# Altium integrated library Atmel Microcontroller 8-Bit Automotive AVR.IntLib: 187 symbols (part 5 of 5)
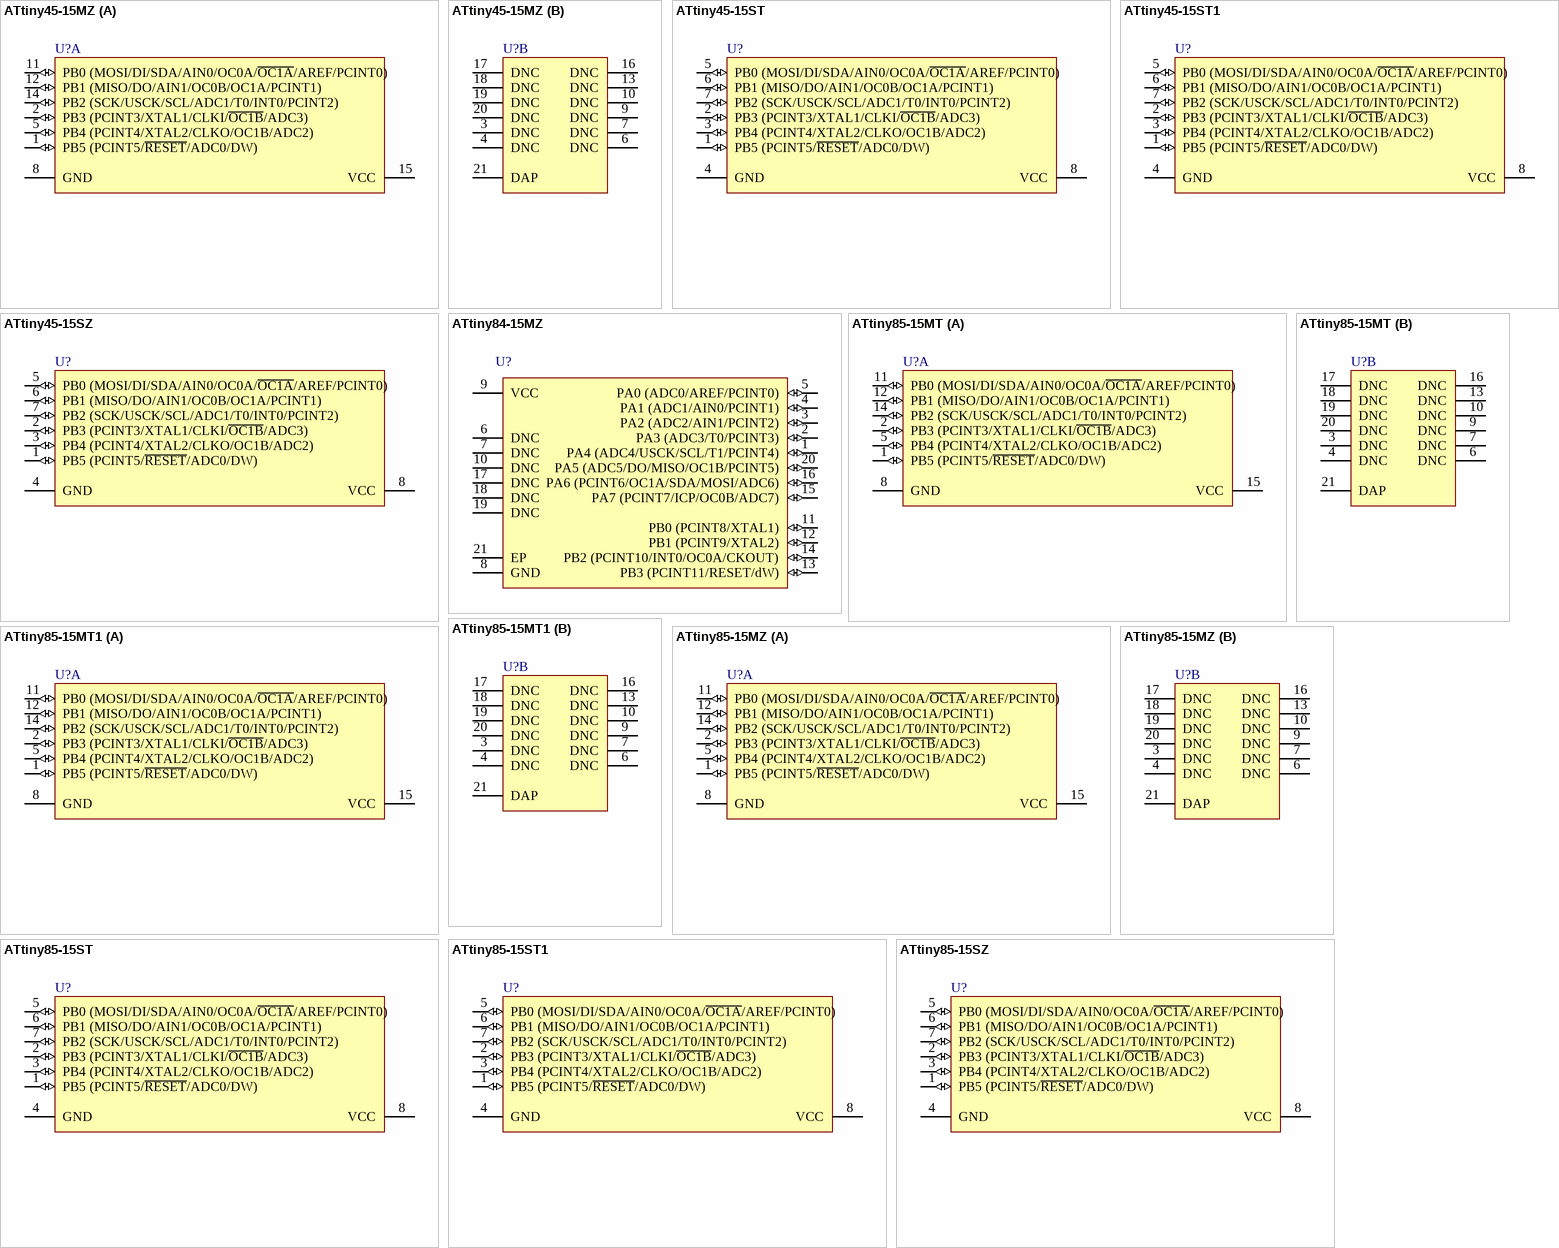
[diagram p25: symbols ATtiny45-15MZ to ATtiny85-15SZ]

## ATtiny85-15MT1
designator U?
8-bit Automotive AVR Microcontroller, 8KB Flash, 512 Bytes EEPROM, 512 Bytes SRAM, Automotive Grade (-40°C to +105°C), 20-Pin VQFN
footprint 20PC_N (QFN, 20-Leads, Body 4x4mm, Pitch 0.5mm, IPC Medium Density)
footprint 20PC_L (QFN, 20-Leads, Body 4x4mm, Pitch 0.5mm, IPC High Density)
footprint 20PC_M (QFN, 20-Leads, Body 4x4mm, Pitch 0.5mm, IPC Low Density)
part A pins: 1 PB5 (PCINT5/~{RESET}/ADC0/DW) (io), 2 PB3 (PCINT3/XTAL1/CLKI/~{OC1B}/ADC3) (io), 5 PB4 (PCINT4/XTAL2/CLKO/OC1B/ADC2) (io), 8 GND (power), 11 PB0 (MOSI/DI/SDA/AIN0/OC0A/~{OC1A}/AREF/PCINT0) (io), 12 PB1 (MISO/DO/AIN1/OC0B/OC1A/PCINT1) (io), 14 PB2 (SCK/USCK/SCL/ADC1/T0/INT0/PCINT2) (io), 15 VCC (power)
part B pins: 3 DNC, 4 DNC, 6 DNC, 7 DNC, 9 DNC, 10 DNC, 13 DNC, 16 DNC, 17 DNC, 18 DNC, 19 DNC, 20 DNC, 21 DAP

## ATtiny85-15MZ
designator U?
8-bit Automotive AVR Microcontroller, 8KB Flash, 512 Bytes EEPROM, 512 Bytes SRAM, Automotive Grade (-40°C to +125°C), 20-Pin VQFN
footprint 20PC_N (QFN, 20-Leads, Body 4x4mm, Pitch 0.5mm, IPC Medium Density)
footprint 20PC_L (QFN, 20-Leads, Body 4x4mm, Pitch 0.5mm, IPC High Density)
footprint 20PC_M (QFN, 20-Leads, Body 4x4mm, Pitch 0.5mm, IPC Low Density)
part A pins: 1 PB5 (PCINT5/~{RESET}/ADC0/DW) (io), 2 PB3 (PCINT3/XTAL1/CLKI/~{OC1B}/ADC3) (io), 5 PB4 (PCINT4/XTAL2/CLKO/OC1B/ADC2) (io), 8 GND (power), 11 PB0 (MOSI/DI/SDA/AIN0/OC0A/~{OC1A}/AREF/PCINT0) (io), 12 PB1 (MISO/DO/AIN1/OC0B/OC1A/PCINT1) (io), 14 PB2 (SCK/USCK/SCL/ADC1/T0/INT0/PCINT2) (io), 15 VCC (power)
part B pins: 3 DNC, 4 DNC, 6 DNC, 7 DNC, 9 DNC, 10 DNC, 13 DNC, 16 DNC, 17 DNC, 18 DNC, 19 DNC, 20 DNC, 21 DAP

## ATtiny85-15ST
designator U?
8-bit Automotive AVR Microcontroller, 8KB Flash, 512 Bytes EEPROM, 512 Bytes SRAM, Automotive Grade (-40°C to +85°C), 8-Pin SOIC
footprint T5_N (SOP, 8-Leads, Body 5.2x5.3mm, Pitch 1.27mm, IPC Medium Density)
footprint T5_L (SOP, 8-Leads, Body 5.2x5.3mm, Pitch 1.27mm, IPC High Density)
footprint T5_M (SOP, 8-Leads, Body 5.2x5.3mm, Pitch 1.27mm, IPC Low Density)
pins: 1 PB5 (PCINT5/~{RESET}/ADC0/DW) (io), 2 PB3 (PCINT3/XTAL1/CLKI/~{OC1B}/ADC3) (io), 3 PB4 (PCINT4/XTAL2/CLKO/OC1B/ADC2) (io), 4 GND (power), 5 PB0 (MOSI/DI/SDA/AIN0/OC0A/~{OC1A}/AREF/PCINT0) (io), 6 PB1 (MISO/DO/AIN1/OC0B/OC1A/PCINT1) (io), 7 PB2 (SCK/USCK/SCL/ADC1/T0/INT0/PCINT2) (io), 8 VCC (power)

## ATtiny85-15ST1
designator U?
8-bit Automotive AVR Microcontroller, 8KB Flash, 512 Bytes EEPROM, 512 Bytes SRAM, Automotive Grade (-40°C to +105°C), 8-Pin SOIC
footprint T5_N (SOP, 8-Leads, Body 5.2x5.3mm, Pitch 1.27mm, IPC Medium Density)
footprint T5_L (SOP, 8-Leads, Body 5.2x5.3mm, Pitch 1.27mm, IPC High Density)
footprint T5_M (SOP, 8-Leads, Body 5.2x5.3mm, Pitch 1.27mm, IPC Low Density)
pins: 1 PB5 (PCINT5/~{RESET}/ADC0/DW) (io), 2 PB3 (PCINT3/XTAL1/CLKI/~{OC1B}/ADC3) (io), 3 PB4 (PCINT4/XTAL2/CLKO/OC1B/ADC2) (io), 4 GND (power), 5 PB0 (MOSI/DI/SDA/AIN0/OC0A/~{OC1A}/AREF/PCINT0) (io), 6 PB1 (MISO/DO/AIN1/OC0B/OC1A/PCINT1) (io), 7 PB2 (SCK/USCK/SCL/ADC1/T0/INT0/PCINT2) (io), 8 VCC (power)

## ATtiny85-15SZ
designator U?
8-bit Automotive AVR Microcontroller, 8KB Flash, 512 Bytes EEPROM, 512 Bytes SRAM, Automotive Grade (-40°C to +125°C), 8-Pin SOIC
footprint T5_N (SOP, 8-Leads, Body 5.2x5.3mm, Pitch 1.27mm, IPC Medium Density)
footprint T5_L (SOP, 8-Leads, Body 5.2x5.3mm, Pitch 1.27mm, IPC High Density)
footprint T5_M (SOP, 8-Leads, Body 5.2x5.3mm, Pitch 1.27mm, IPC Low Density)
pins: 1 PB5 (PCINT5/~{RESET}/ADC0/DW) (io), 2 PB3 (PCINT3/XTAL1/CLKI/~{OC1B}/ADC3) (io), 3 PB4 (PCINT4/XTAL2/CLKO/OC1B/ADC2) (io), 4 GND (power), 5 PB0 (MOSI/DI/SDA/AIN0/OC0A/~{OC1A}/AREF/PCINT0) (io), 6 PB1 (MISO/DO/AIN1/OC0B/OC1A/PCINT1) (io), 7 PB2 (SCK/USCK/SCL/ADC1/T0/INT0/PCINT2) (io), 8 VCC (power)

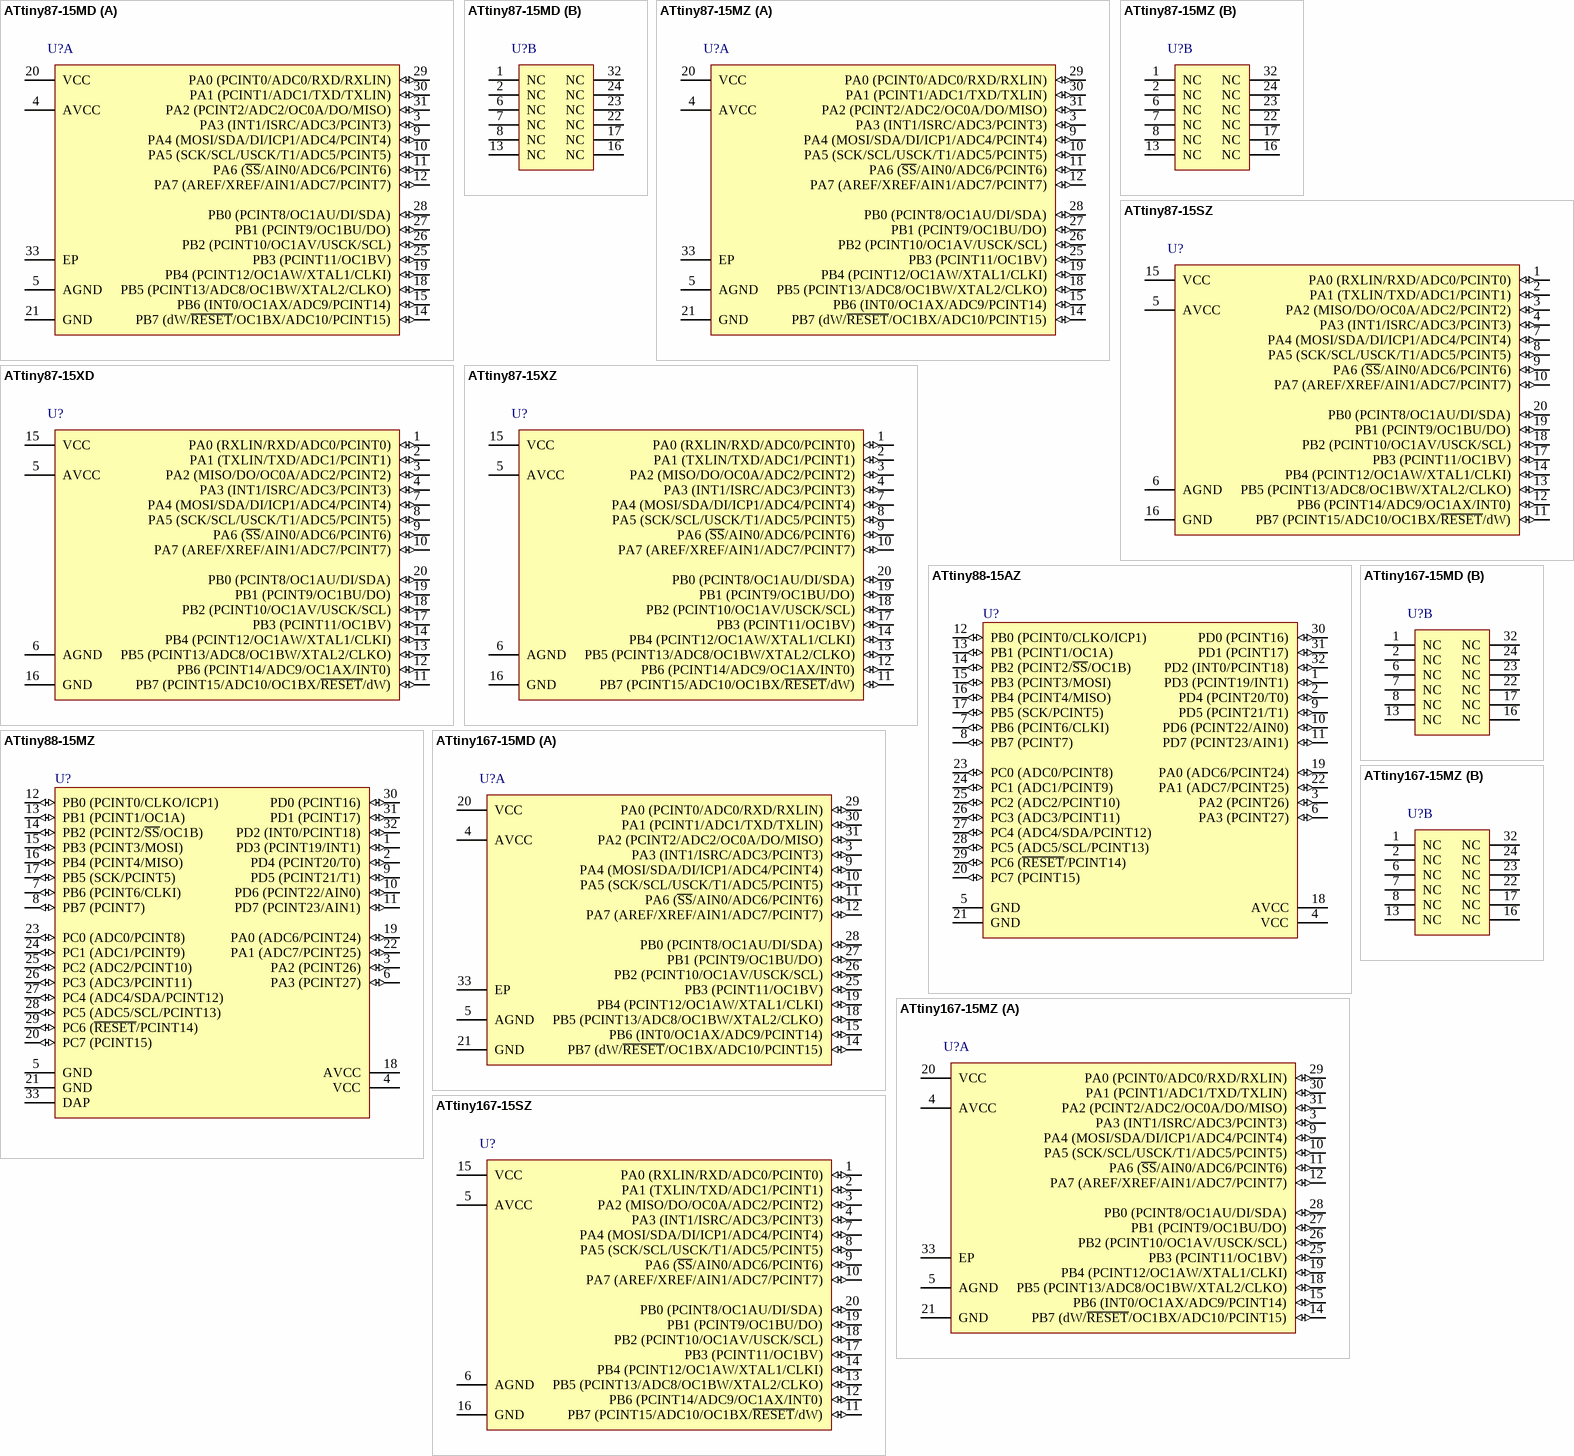
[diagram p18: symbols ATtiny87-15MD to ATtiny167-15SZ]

## ATtiny87-15MD
designator U?
8-bit Automotive AVR Microcontroller, 8KB Flash, 512 Bytes EEPROM, 512 Bytes SRAM, Extended Grade (-40°C to +150°C), 32-Pin VQFN
footprint 32PN_N (QFN, 32-Leads, Body 5x5mm, Pitch 0.5mm, IPC Medium Density)
footprint 32PN_L (QFN, 32-Leads, Body 5x5mm, Pitch 0.5mm, IPC High Density)
footprint 32PN_M (QFN, 32-Leads, Body 5x5mm, Pitch 0.5mm, IPC Low Density)
part A pins: 3 PA3 (INT1/ISRC/ADC3/PCINT3) (io), 4 AVCC (power), 5 AGND (power), 9 PA4 (MOSI/SDA/DI/ICP1/ADC4/PCINT4) (io), 10 PA5 (SCK/SCL/USCK/T1/ADC5/PCINT5) (io), 11 PA6 (~{SS}/AIN0/ADC6/PCINT6) (io), 12 PA7 (AREF/XREF/AIN1/ADC7/PCINT7) (io), 14 PB7 (dW/~{RESET}/OC1BX/ADC10/PCINT15) (io), 15 PB6 (INT0/OC1AX/ADC9/PCINT14) (io), 18 PB5 (PCINT13/ADC8/OC1BW/XTAL2/CLKO) (io), 19 PB4 (PCINT12/OC1AW/XTAL1/CLKI) (io), 20 VCC (power), 21 GND (power), 25 PB3 (PCINT11/OC1BV) (io), 26 PB2 (PCINT10/OC1AV/USCK/SCL) (io), 27 PB1 (PCINT9/OC1BU/DO) (io), 28 PB0 (PCINT8/OC1AU/DI/SDA) (io), 29 PA0 (PCINT0/ADC0/RXD/RXLIN) (io), 30 PA1 (PCINT1/ADC1/TXD/TXLIN) (io), 31 PA2 (PCINT2/ADC2/OC0A/DO/MISO) (io), 33 EP (power)
part B pins: 1 NC, 2 NC, 6 NC, 7 NC, 8 NC, 13 NC, 16 NC, 17 NC, 22 NC, 23 NC, 24 NC, 32 NC

## ATtiny87-15MZ
designator U?
8-bit Automotive AVR Microcontroller, 8KB Flash, 512 Bytes EEPROM, 512 Bytes SRAM, Automotive Grade (-40°C to +125°C), 32-Pin VQFN
footprint 32PN_N (QFN, 32-Leads, Body 5x5mm, Pitch 0.5mm, IPC Medium Density)
footprint 32PN_L (QFN, 32-Leads, Body 5x5mm, Pitch 0.5mm, IPC High Density)
footprint 32PN_M (QFN, 32-Leads, Body 5x5mm, Pitch 0.5mm, IPC Low Density)
part A pins: 3 PA3 (INT1/ISRC/ADC3/PCINT3) (io), 4 AVCC (power), 5 AGND (power), 9 PA4 (MOSI/SDA/DI/ICP1/ADC4/PCINT4) (io), 10 PA5 (SCK/SCL/USCK/T1/ADC5/PCINT5) (io), 11 PA6 (~{SS}/AIN0/ADC6/PCINT6) (io), 12 PA7 (AREF/XREF/AIN1/ADC7/PCINT7) (io), 14 PB7 (dW/~{RESET}/OC1BX/ADC10/PCINT15) (io), 15 PB6 (INT0/OC1AX/ADC9/PCINT14) (io), 18 PB5 (PCINT13/ADC8/OC1BW/XTAL2/CLKO) (io), 19 PB4 (PCINT12/OC1AW/XTAL1/CLKI) (io), 20 VCC (power), 21 GND (power), 25 PB3 (PCINT11/OC1BV) (io), 26 PB2 (PCINT10/OC1AV/USCK/SCL) (io), 27 PB1 (PCINT9/OC1BU/DO) (io), 28 PB0 (PCINT8/OC1AU/DI/SDA) (io), 29 PA0 (PCINT0/ADC0/RXD/RXLIN) (io), 30 PA1 (PCINT1/ADC1/TXD/TXLIN) (io), 31 PA2 (PCINT2/ADC2/OC0A/DO/MISO) (io), 33 EP (power)
part B pins: 1 NC, 2 NC, 6 NC, 7 NC, 8 NC, 13 NC, 16 NC, 17 NC, 22 NC, 23 NC, 24 NC, 32 NC

## ATtiny87-15SZ
designator U?
8-bit Automotive AVR Microcontroller, 8KB Flash, 512 Bytes EEPROM, 512 Bytes SRAM, Automotive Grade (-40°C to +125°C), 20-Pin SOIC
footprint 20TG_N (SOIC, 20-Leads, Body 12.8x7.5mm, Pitch 1.27mm, IPC Medium Density)
footprint 20TG_L (SOIC, 20-Leads, Body 12.8x7.5mm, Pitch 1.27mm, IPC High Density)
footprint 20TG_M (SOIC, 20-Leads, Body 12.8x7.5mm, Pitch 1.27mm, IPC Low Density)
pins: 1 PA0 (RXLIN/RXD/ADC0/PCINT0) (io), 2 PA1 (TXLIN/TXD/ADC1/PCINT1) (io), 3 PA2 (MISO/DO/OC0A/ADC2/PCINT2) (io), 4 PA3 (INT1/ISRC/ADC3/PCINT3) (io), 5 AVCC (power), 6 AGND (power), 7 PA4 (MOSI/SDA/DI/ICP1/ADC4/PCINT4) (io), 8 PA5 (SCK/SCL/USCK/T1/ADC5/PCINT5) (io), 9 PA6 (~{SS}/AIN0/ADC6/PCINT6) (io), 10 PA7 (AREF/XREF/AIN1/ADC7/PCINT7) (io), 11 PB7 (PCINT15/ADC10/OC1BX/~{RESET}/dW) (io), 12 PB6 (PCINT14/ADC9/OC1AX/INT0) (io), 13 PB5 (PCINT13/ADC8/OC1BW/XTAL2/CLKO) (io), 14 PB4 (PCINT12/OC1AW/XTAL1/CLKI) (io), 15 VCC (power), 16 GND (power), 17 PB3 (PCINT11/OC1BV) (io), 18 PB2 (PCINT10/OC1AV/USCK/SCL) (io), 19 PB1 (PCINT9/OC1BU/DO) (io), 20 PB0 (PCINT8/OC1AU/DI/SDA) (io)

## ATtiny87-15XD
designator U?
8-bit Automotive AVR Microcontroller, 8KB Flash, 512 Bytes EEPROM, 512 Bytes SRAM, Extended Grade (-40°C to +150°C), 20-Pin TSSOP
footprint 6G_N (TSOP, 20-Leads, Body 6.5x4.4mm, Pitch 0.65mm, IPC Medium Density)
footprint 6G_L (TSOP, 20-Leads, Body 6.5x4.4mm, Pitch 0.65mm, IPC High Density)
footprint 6G_M (TSOP, 20-Leads, Body 6.5x4.4mm, Pitch 0.65mm, IPC Low Density)
pins: 1 PA0 (RXLIN/RXD/ADC0/PCINT0) (io), 2 PA1 (TXLIN/TXD/ADC1/PCINT1) (io), 3 PA2 (MISO/DO/OC0A/ADC2/PCINT2) (io), 4 PA3 (INT1/ISRC/ADC3/PCINT3) (io), 5 AVCC (power), 6 AGND (power), 7 PA4 (MOSI/SDA/DI/ICP1/ADC4/PCINT4) (io), 8 PA5 (SCK/SCL/USCK/T1/ADC5/PCINT5) (io), 9 PA6 (~{SS}/AIN0/ADC6/PCINT6) (io), 10 PA7 (AREF/XREF/AIN1/ADC7/PCINT7) (io), 11 PB7 (PCINT15/ADC10/OC1BX/~{RESET}/dW) (io), 12 PB6 (PCINT14/ADC9/OC1AX/INT0) (io), 13 PB5 (PCINT13/ADC8/OC1BW/XTAL2/CLKO) (io), 14 PB4 (PCINT12/OC1AW/XTAL1/CLKI) (io), 15 VCC (power), 16 GND (power), 17 PB3 (PCINT11/OC1BV) (io), 18 PB2 (PCINT10/OC1AV/USCK/SCL) (io), 19 PB1 (PCINT9/OC1BU/DO) (io), 20 PB0 (PCINT8/OC1AU/DI/SDA) (io)

## ATtiny87-15XZ
designator U?
8-bit Automotive AVR Microcontroller, 8KB Flash, 512 Bytes EEPROM, 512 Bytes SRAM, Automotive Grade (-40°C to +125°C), 20-Pin TSSOP
footprint 6G_N (TSOP, 20-Leads, Body 6.5x4.4mm, Pitch 0.65mm, IPC Medium Density)
footprint 6G_L (TSOP, 20-Leads, Body 6.5x4.4mm, Pitch 0.65mm, IPC High Density)
footprint 6G_M (TSOP, 20-Leads, Body 6.5x4.4mm, Pitch 0.65mm, IPC Low Density)
pins: 1 PA0 (RXLIN/RXD/ADC0/PCINT0) (io), 2 PA1 (TXLIN/TXD/ADC1/PCINT1) (io), 3 PA2 (MISO/DO/OC0A/ADC2/PCINT2) (io), 4 PA3 (INT1/ISRC/ADC3/PCINT3) (io), 5 AVCC (power), 6 AGND (power), 7 PA4 (MOSI/SDA/DI/ICP1/ADC4/PCINT4) (io), 8 PA5 (SCK/SCL/USCK/T1/ADC5/PCINT5) (io), 9 PA6 (~{SS}/AIN0/ADC6/PCINT6) (io), 10 PA7 (AREF/XREF/AIN1/ADC7/PCINT7) (io), 11 PB7 (PCINT15/ADC10/OC1BX/~{RESET}/dW) (io), 12 PB6 (PCINT14/ADC9/OC1AX/INT0) (io), 13 PB5 (PCINT13/ADC8/OC1BW/XTAL2/CLKO) (io), 14 PB4 (PCINT12/OC1AW/XTAL1/CLKI) (io), 15 VCC (power), 16 GND (power), 17 PB3 (PCINT11/OC1BV) (io), 18 PB2 (PCINT10/OC1AV/USCK/SCL) (io), 19 PB1 (PCINT9/OC1BU/DO) (io), 20 PB0 (PCINT8/OC1AU/DI/SDA) (io)

## ATtiny88-15AZ
designator U?
8-bit Automotive AVR Microcontroller, 8KB Flash, 64 Bytes EEPROM, 512 Bytes SRAM, Automotive Grade (-40°C to +125°C), 32-Pin TQFP
footprint 32MA_N (Thin QFP, 32-Leads, Body 7x7mm, Pitch 0.8mm, IPC Medium Density)
footprint 32MA_L (Thin QFP, 32-Leads, Body 7x7mm, Pitch 0.8mm, IPC High Density)
footprint 32MA_M (Thin QFP, 32-Leads, Body 7x7mm, Pitch 0.8mm, IPC Low Density)
pins: 1 PD3 (PCINT19/INT1) (io), 2 PD4 (PCINT20/T0) (io), 3 PA2 (PCINT26) (io), 4 VCC (power), 5 GND (power), 6 PA3 (PCINT27) (io), 7 PB6 (PCINT6/CLKI) (io), 8 PB7 (PCINT7) (io), 9 PD5 (PCINT21/T1) (io), 10 PD6 (PCINT22/AIN0) (io), 11 PD7 (PCINT23/AIN1) (io), 12 PB0 (PCINT0/CLKO/ICP1) (io), 13 PB1 (PCINT1/OC1A) (io), 14 PB2 (PCINT2/~{SS}/OC1B) (io), 15 PB3 (PCINT3/MOSI) (io), 16 PB4 (PCINT4/MISO) (io), 17 PB5 (SCK/PCINT5) (io), 18 AVCC (power), 19 PA0 (ADC6/PCINT24) (io), 20 PC7 (PCINT15) (io), 21 GND (power), 22 PA1 (ADC7/PCINT25) (io), 23 PC0 (ADC0/PCINT8) (io), 24 PC1 (ADC1/PCINT9) (io), 25 PC2 (ADC2/PCINT10) (io), 26 PC3 (ADC3/PCINT11) (io), 27 PC4 (ADC4/SDA/PCINT12) (io), 28 PC5 (ADC5/SCL/PCINT13) (io), 29 PC6 (~{RESET}/PCINT14) (io), 30 PD0 (PCINT16) (io), 31 PD1 (PCINT17) (io), 32 PD2 (INT0/PCINT18) (io)

## ATtiny88-15MZ
designator U?
8-bit Automotive AVR Microcontroller, 8KB Flash, 64 Bytes EEPROM, 512 Bytes SRAM, Automotive Grade (-40°C to +125°C), 32-Pin VQFN
footprint 32PN_N (QFN, 32-Leads, Body 5x5mm, Pitch 0.5mm, IPC Medium Density)
footprint 32PN_L (QFN, 32-Leads, Body 5x5mm, Pitch 0.5mm, IPC High Density)
footprint 32PN_M (QFN, 32-Leads, Body 5x5mm, Pitch 0.5mm, IPC Low Density)
pins: 1 PD3 (PCINT19/INT1) (io), 2 PD4 (PCINT20/T0) (io), 3 PA2 (PCINT26) (io), 4 VCC (power), 5 GND (power), 6 PA3 (PCINT27) (io), 7 PB6 (PCINT6/CLKI) (io), 8 PB7 (PCINT7) (io), 9 PD5 (PCINT21/T1) (io), 10 PD6 (PCINT22/AIN0) (io), 11 PD7 (PCINT23/AIN1) (io), 12 PB0 (PCINT0/CLKO/ICP1) (io), 13 PB1 (PCINT1/OC1A) (io), 14 PB2 (PCINT2/~{SS}/OC1B) (io), 15 PB3 (PCINT3/MOSI) (io), 16 PB4 (PCINT4/MISO) (io), 17 PB5 (SCK/PCINT5) (io), 18 AVCC (power), 19 PA0 (ADC6/PCINT24) (io), 20 PC7 (PCINT15) (io), 21 GND (power), 22 PA1 (ADC7/PCINT25) (io), 23 PC0 (ADC0/PCINT8) (io), 24 PC1 (ADC1/PCINT9) (io), 25 PC2 (ADC2/PCINT10) (io), 26 PC3 (ADC3/PCINT11) (io), 27 PC4 (ADC4/SDA/PCINT12) (io), 28 PC5 (ADC5/SCL/PCINT13) (io), 29 PC6 (~{RESET}/PCINT14) (io), 30 PD0 (PCINT16) (io), 31 PD1 (PCINT17) (io), 32 PD2 (INT0/PCINT18) (io), 33 DAP

## ATtiny167-15MD
designator U?
8-bit Automotive AVR Microcontroller, 16KB Flash, 512 Bytes EEPROM, 512 Bytes SRAM, Extended Grade (-40°C to +150°C), 32-Pin VQFN
footprint 32PN_N (QFN, 32-Leads, Body 5x5mm, Pitch 0.5mm, IPC Medium Density)
footprint 32PN_L (QFN, 32-Leads, Body 5x5mm, Pitch 0.5mm, IPC High Density)
footprint 32PN_M (QFN, 32-Leads, Body 5x5mm, Pitch 0.5mm, IPC Low Density)
part A pins: 3 PA3 (INT1/ISRC/ADC3/PCINT3) (io), 4 AVCC (power), 5 AGND (power), 9 PA4 (MOSI/SDA/DI/ICP1/ADC4/PCINT4) (io), 10 PA5 (SCK/SCL/USCK/T1/ADC5/PCINT5) (io), 11 PA6 (~{SS}/AIN0/ADC6/PCINT6) (io), 12 PA7 (AREF/XREF/AIN1/ADC7/PCINT7) (io), 14 PB7 (dW/~{RESET}/OC1BX/ADC10/PCINT15) (io), 15 PB6 (INT0/OC1AX/ADC9/PCINT14) (io), 18 PB5 (PCINT13/ADC8/OC1BW/XTAL2/CLKO) (io), 19 PB4 (PCINT12/OC1AW/XTAL1/CLKI) (io), 20 VCC (power), 21 GND (power), 25 PB3 (PCINT11/OC1BV) (io), 26 PB2 (PCINT10/OC1AV/USCK/SCL) (io), 27 PB1 (PCINT9/OC1BU/DO) (io), 28 PB0 (PCINT8/OC1AU/DI/SDA) (io), 29 PA0 (PCINT0/ADC0/RXD/RXLIN) (io), 30 PA1 (PCINT1/ADC1/TXD/TXLIN) (io), 31 PA2 (PCINT2/ADC2/OC0A/DO/MISO) (io), 33 EP (power)
part B pins: 1 NC, 2 NC, 6 NC, 7 NC, 8 NC, 13 NC, 16 NC, 17 NC, 22 NC, 23 NC, 24 NC, 32 NC

## ATtiny167-15MZ
designator U?
8-bit Automotive AVR Microcontroller, 16KB Flash, 512 Bytes EEPROM, 512 Bytes SRAM, Automotive Grade (-40°C to +125°C), 32-Pin VQFN
footprint 32PN_N (QFN, 32-Leads, Body 5x5mm, Pitch 0.5mm, IPC Medium Density)
footprint 32PN_L (QFN, 32-Leads, Body 5x5mm, Pitch 0.5mm, IPC High Density)
footprint 32PN_M (QFN, 32-Leads, Body 5x5mm, Pitch 0.5mm, IPC Low Density)
part A pins: 3 PA3 (INT1/ISRC/ADC3/PCINT3) (io), 4 AVCC (power), 5 AGND (power), 9 PA4 (MOSI/SDA/DI/ICP1/ADC4/PCINT4) (io), 10 PA5 (SCK/SCL/USCK/T1/ADC5/PCINT5) (io), 11 PA6 (~{SS}/AIN0/ADC6/PCINT6) (io), 12 PA7 (AREF/XREF/AIN1/ADC7/PCINT7) (io), 14 PB7 (dW/~{RESET}/OC1BX/ADC10/PCINT15) (io), 15 PB6 (INT0/OC1AX/ADC9/PCINT14) (io), 18 PB5 (PCINT13/ADC8/OC1BW/XTAL2/CLKO) (io), 19 PB4 (PCINT12/OC1AW/XTAL1/CLKI) (io), 20 VCC (power), 21 GND (power), 25 PB3 (PCINT11/OC1BV) (io), 26 PB2 (PCINT10/OC1AV/USCK/SCL) (io), 27 PB1 (PCINT9/OC1BU/DO) (io), 28 PB0 (PCINT8/OC1AU/DI/SDA) (io), 29 PA0 (PCINT0/ADC0/RXD/RXLIN) (io), 30 PA1 (PCINT1/ADC1/TXD/TXLIN) (io), 31 PA2 (PCINT2/ADC2/OC0A/DO/MISO) (io), 33 EP (power)
part B pins: 1 NC, 2 NC, 6 NC, 7 NC, 8 NC, 13 NC, 16 NC, 17 NC, 22 NC, 23 NC, 24 NC, 32 NC

## ATtiny167-15SZ
designator U?
8-bit Automotive AVR Microcontroller, 16KB Flash, 512 Bytes EEPROM, 512 Bytes SRAM, Automotive Grade (-40°C to +125°C), 20-Pin SOIC
footprint 20TG_N (SOIC, 20-Leads, Body 12.8x7.5mm, Pitch 1.27mm, IPC Medium Density)
footprint 20TG_L (SOIC, 20-Leads, Body 12.8x7.5mm, Pitch 1.27mm, IPC High Density)
footprint 20TG_M (SOIC, 20-Leads, Body 12.8x7.5mm, Pitch 1.27mm, IPC Low Density)
pins: 1 PA0 (RXLIN/RXD/ADC0/PCINT0) (io), 2 PA1 (TXLIN/TXD/ADC1/PCINT1) (io), 3 PA2 (MISO/DO/OC0A/ADC2/PCINT2) (io), 4 PA3 (INT1/ISRC/ADC3/PCINT3) (io), 5 AVCC (power), 6 AGND (power), 7 PA4 (MOSI/SDA/DI/ICP1/ADC4/PCINT4) (io), 8 PA5 (SCK/SCL/USCK/T1/ADC5/PCINT5) (io), 9 PA6 (~{SS}/AIN0/ADC6/PCINT6) (io), 10 PA7 (AREF/XREF/AIN1/ADC7/PCINT7) (io), 11 PB7 (PCINT15/ADC10/OC1BX/~{RESET}/dW) (io), 12 PB6 (PCINT14/ADC9/OC1AX/INT0) (io), 13 PB5 (PCINT13/ADC8/OC1BW/XTAL2/CLKO) (io), 14 PB4 (PCINT12/OC1AW/XTAL1/CLKI) (io), 15 VCC (power), 16 GND (power), 17 PB3 (PCINT11/OC1BV) (io), 18 PB2 (PCINT10/OC1AV/USCK/SCL) (io), 19 PB1 (PCINT9/OC1BU/DO) (io), 20 PB0 (PCINT8/OC1AU/DI/SDA) (io)

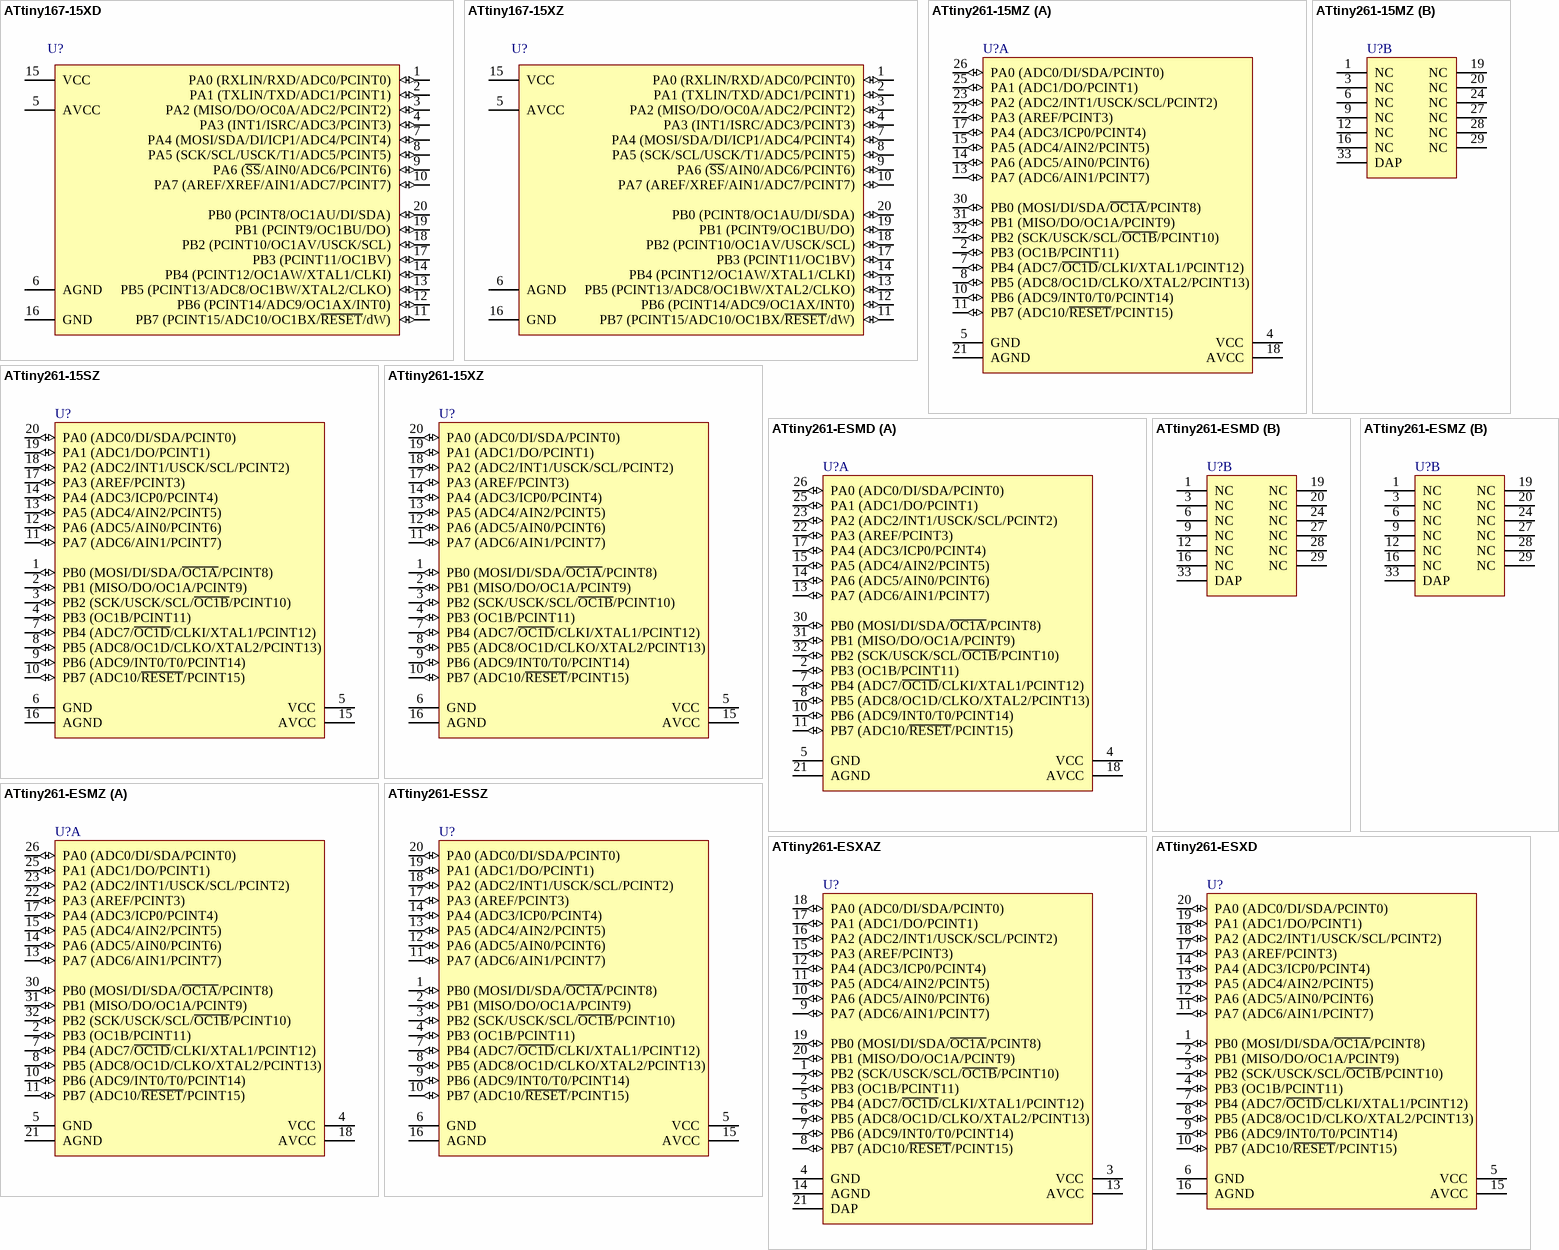
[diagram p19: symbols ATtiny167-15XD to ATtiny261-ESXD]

## ATtiny167-15XD
designator U?
8-bit Automotive AVR Microcontroller, 16KB Flash, 512 Bytes EEPROM, 512 Bytes SRAM, Extended Grade (-40°C to +150°C), 20-Pin TSSOP
footprint 6G_N (TSOP, 20-Leads, Body 6.5x4.4mm, Pitch 0.65mm, IPC Medium Density)
footprint 6G_L (TSOP, 20-Leads, Body 6.5x4.4mm, Pitch 0.65mm, IPC High Density)
footprint 6G_M (TSOP, 20-Leads, Body 6.5x4.4mm, Pitch 0.65mm, IPC Low Density)
pins: 1 PA0 (RXLIN/RXD/ADC0/PCINT0) (io), 2 PA1 (TXLIN/TXD/ADC1/PCINT1) (io), 3 PA2 (MISO/DO/OC0A/ADC2/PCINT2) (io), 4 PA3 (INT1/ISRC/ADC3/PCINT3) (io), 5 AVCC (power), 6 AGND (power), 7 PA4 (MOSI/SDA/DI/ICP1/ADC4/PCINT4) (io), 8 PA5 (SCK/SCL/USCK/T1/ADC5/PCINT5) (io), 9 PA6 (~{SS}/AIN0/ADC6/PCINT6) (io), 10 PA7 (AREF/XREF/AIN1/ADC7/PCINT7) (io), 11 PB7 (PCINT15/ADC10/OC1BX/~{RESET}/dW) (io), 12 PB6 (PCINT14/ADC9/OC1AX/INT0) (io), 13 PB5 (PCINT13/ADC8/OC1BW/XTAL2/CLKO) (io), 14 PB4 (PCINT12/OC1AW/XTAL1/CLKI) (io), 15 VCC (power), 16 GND (power), 17 PB3 (PCINT11/OC1BV) (io), 18 PB2 (PCINT10/OC1AV/USCK/SCL) (io), 19 PB1 (PCINT9/OC1BU/DO) (io), 20 PB0 (PCINT8/OC1AU/DI/SDA) (io)

## ATtiny167-15XZ
designator U?
8-bit Automotive AVR Microcontroller, 16KB Flash, 512 Bytes EEPROM, 512 Bytes SRAM, Automotive Grade (-40°C to +125°C), 20-Pin TSSOP
footprint 6G_N (TSOP, 20-Leads, Body 6.5x4.4mm, Pitch 0.65mm, IPC Medium Density)
footprint 6G_L (TSOP, 20-Leads, Body 6.5x4.4mm, Pitch 0.65mm, IPC High Density)
footprint 6G_M (TSOP, 20-Leads, Body 6.5x4.4mm, Pitch 0.65mm, IPC Low Density)
pins: 1 PA0 (RXLIN/RXD/ADC0/PCINT0) (io), 2 PA1 (TXLIN/TXD/ADC1/PCINT1) (io), 3 PA2 (MISO/DO/OC0A/ADC2/PCINT2) (io), 4 PA3 (INT1/ISRC/ADC3/PCINT3) (io), 5 AVCC (power), 6 AGND (power), 7 PA4 (MOSI/SDA/DI/ICP1/ADC4/PCINT4) (io), 8 PA5 (SCK/SCL/USCK/T1/ADC5/PCINT5) (io), 9 PA6 (~{SS}/AIN0/ADC6/PCINT6) (io), 10 PA7 (AREF/XREF/AIN1/ADC7/PCINT7) (io), 11 PB7 (PCINT15/ADC10/OC1BX/~{RESET}/dW) (io), 12 PB6 (PCINT14/ADC9/OC1AX/INT0) (io), 13 PB5 (PCINT13/ADC8/OC1BW/XTAL2/CLKO) (io), 14 PB4 (PCINT12/OC1AW/XTAL1/CLKI) (io), 15 VCC (power), 16 GND (power), 17 PB3 (PCINT11/OC1BV) (io), 18 PB2 (PCINT10/OC1AV/USCK/SCL) (io), 19 PB1 (PCINT9/OC1BU/DO) (io), 20 PB0 (PCINT8/OC1AU/DI/SDA) (io)

## ATtiny261-15MZ
designator U?
8-bit Automotive AVR Microcontroller, 2KB Flash, 128 Bytes EEPROM, 128 Bytes SRAM, Automotive Grade (-40°C to +125°C), 32-Pin VQFN
footprint 32PN_N (QFN, 32-Leads, Body 5x5mm, Pitch 0.5mm, IPC Medium Density)
footprint 32PN_L (QFN, 32-Leads, Body 5x5mm, Pitch 0.5mm, IPC High Density)
footprint 32PN_M (QFN, 32-Leads, Body 5x5mm, Pitch 0.5mm, IPC Low Density)
part A pins: 2 PB3 (OC1B/PCINT11) (io), 4 VCC (power), 5 GND (power), 7 PB4 (ADC7/~{OC1D}/CLKI/XTAL1/PCINT12) (io), 8 PB5 (ADC8/OC1D/CLKO/XTAL2/PCINT13) (io), 10 PB6 (ADC9/INT0/T0/PCINT14) (io), 11 PB7 (ADC10/~{RESET}/PCINT15) (io), 13 PA7 (ADC6/AIN1/PCINT7) (io), 14 PA6 (ADC5/AIN0/PCINT6) (io), 15 PA5 (ADC4/AIN2/PCINT5) (io), 17 PA4 (ADC3/ICP0/PCINT4) (io), 18 AVCC (power), 21 AGND (power), 22 PA3 (AREF/PCINT3) (io), 23 PA2 (ADC2/INT1/USCK/SCL/PCINT2) (io), 25 PA1 (ADC1/DO/PCINT1) (io), 26 PA0 (ADC0/DI/SDA/PCINT0) (io), 30 PB0 (MOSI/DI/SDA/~{OC1A}/PCINT8) (io), 31 PB1 (MISO/DO/OC1A/PCINT9) (io), 32 PB2 (SCK/USCK/SCL/~{OC1B}/PCINT10) (io)
part B pins: 1 NC, 3 NC, 6 NC, 9 NC, 12 NC, 16 NC, 19 NC, 20 NC, 24 NC, 27 NC, 28 NC, 29 NC, 33 DAP (power)

## ATtiny261-15SZ
designator U?
8-bit Automotive AVR Microcontroller, 2KB Flash, 128 Bytes EEPROM, 128 Bytes SRAM, Automotive Grade (-40°C to +125°C), 20-Pin SOIC
footprint 20TG_N (SOIC, 20-Leads, Body 12.8x7.5mm, Pitch 1.27mm, IPC Medium Density)
footprint 20TG_L (SOIC, 20-Leads, Body 12.8x7.5mm, Pitch 1.27mm, IPC High Density)
footprint 20TG_M (SOIC, 20-Leads, Body 12.8x7.5mm, Pitch 1.27mm, IPC Low Density)
pins: 1 PB0 (MOSI/DI/SDA/~{OC1A}/PCINT8) (io), 2 PB1 (MISO/DO/OC1A/PCINT9) (io), 3 PB2 (SCK/USCK/SCL/~{OC1B}/PCINT10) (io), 4 PB3 (OC1B/PCINT11) (io), 5 VCC (power), 6 GND (power), 7 PB4 (ADC7/~{OC1D}/CLKI/XTAL1/PCINT12) (io), 8 PB5 (ADC8/OC1D/CLKO/XTAL2/PCINT13) (io), 9 PB6 (ADC9/INT0/T0/PCINT14) (io), 10 PB7 (ADC10/~{RESET}/PCINT15) (io), 11 PA7 (ADC6/AIN1/PCINT7) (io), 12 PA6 (ADC5/AIN0/PCINT6) (io), 13 PA5 (ADC4/AIN2/PCINT5) (io), 14 PA4 (ADC3/ICP0/PCINT4) (io), 15 AVCC (power), 16 AGND (power), 17 PA3 (AREF/PCINT3) (io), 18 PA2 (ADC2/INT1/USCK/SCL/PCINT2) (io), 19 PA1 (ADC1/DO/PCINT1) (io), 20 PA0 (ADC0/DI/SDA/PCINT0) (io)

## ATtiny261-15XZ
designator U?
8-bit Automotive AVR Microcontroller, 2KB Flash, 128 Bytes EEPROM, 128 Bytes SRAM, Automotive Grade (-40°C to +125°C), 20-Pin TSSOP
footprint 6G_N (TSOP, 20-Leads, Body 6.5x4.4mm, Pitch 0.65mm, IPC Medium Density)
footprint 6G_L (TSOP, 20-Leads, Body 6.5x4.4mm, Pitch 0.65mm, IPC High Density)
footprint 6G_M (TSOP, 20-Leads, Body 6.5x4.4mm, Pitch 0.65mm, IPC Low Density)
pins: 1 PB0 (MOSI/DI/SDA/~{OC1A}/PCINT8) (io), 2 PB1 (MISO/DO/OC1A/PCINT9) (io), 3 PB2 (SCK/USCK/SCL/~{OC1B}/PCINT10) (io), 4 PB3 (OC1B/PCINT11) (io), 5 VCC (power), 6 GND (power), 7 PB4 (ADC7/~{OC1D}/CLKI/XTAL1/PCINT12) (io), 8 PB5 (ADC8/OC1D/CLKO/XTAL2/PCINT13) (io), 9 PB6 (ADC9/INT0/T0/PCINT14) (io), 10 PB7 (ADC10/~{RESET}/PCINT15) (io), 11 PA7 (ADC6/AIN1/PCINT7) (io), 12 PA6 (ADC5/AIN0/PCINT6) (io), 13 PA5 (ADC4/AIN2/PCINT5) (io), 14 PA4 (ADC3/ICP0/PCINT4) (io), 15 AVCC (power), 16 AGND (power), 17 PA3 (AREF/PCINT3) (io), 18 PA2 (ADC2/INT1/USCK/SCL/PCINT2) (io), 19 PA1 (ADC1/DO/PCINT1) (io), 20 PA0 (ADC0/DI/SDA/PCINT0) (io)

## ATtiny261-ESMD
designator U?
8-bit Automotive AVR Microcontroller, 2KB Flash, 128 Bytes EEPROM, 128 Bytes SRAM, Extended Grade (-40°C to +150°C), 32-Pin VQFN
footprint 32PN_N (QFN, 32-Leads, Body 5x5mm, Pitch 0.5mm, IPC Medium Density)
footprint 32PN_L (QFN, 32-Leads, Body 5x5mm, Pitch 0.5mm, IPC High Density)
footprint 32PN_M (QFN, 32-Leads, Body 5x5mm, Pitch 0.5mm, IPC Low Density)
part A pins: 2 PB3 (OC1B/PCINT11) (io), 4 VCC (power), 5 GND (power), 7 PB4 (ADC7/~{OC1D}/CLKI/XTAL1/PCINT12) (io), 8 PB5 (ADC8/OC1D/CLKO/XTAL2/PCINT13) (io), 10 PB6 (ADC9/INT0/T0/PCINT14) (io), 11 PB7 (ADC10/~{RESET}/PCINT15) (io), 13 PA7 (ADC6/AIN1/PCINT7) (io), 14 PA6 (ADC5/AIN0/PCINT6) (io), 15 PA5 (ADC4/AIN2/PCINT5) (io), 17 PA4 (ADC3/ICP0/PCINT4) (io), 18 AVCC (power), 21 AGND (power), 22 PA3 (AREF/PCINT3) (io), 23 PA2 (ADC2/INT1/USCK/SCL/PCINT2) (io), 25 PA1 (ADC1/DO/PCINT1) (io), 26 PA0 (ADC0/DI/SDA/PCINT0) (io), 30 PB0 (MOSI/DI/SDA/~{OC1A}/PCINT8) (io), 31 PB1 (MISO/DO/OC1A/PCINT9) (io), 32 PB2 (SCK/USCK/SCL/~{OC1B}/PCINT10) (io)
part B pins: 1 NC, 3 NC, 6 NC, 9 NC, 12 NC, 16 NC, 19 NC, 20 NC, 24 NC, 27 NC, 28 NC, 29 NC, 33 DAP (power)

## ATtiny261-ESMZ
designator U?
8-bit Automotive AVR Microcontroller, 2KB Flash, 128 Bytes EEPROM, 128 Bytes SRAM, Automotive Grade (-40°C to +125°C), 32-Pin VQFN, Engineering Sample
footprint 32PN_N (QFN, 32-Leads, Body 5x5mm, Pitch 0.5mm, IPC Medium Density)
footprint 32PN_L (QFN, 32-Leads, Body 5x5mm, Pitch 0.5mm, IPC High Density)
footprint 32PN_M (QFN, 32-Leads, Body 5x5mm, Pitch 0.5mm, IPC Low Density)
part A pins: 2 PB3 (OC1B/PCINT11) (io), 4 VCC (power), 5 GND (power), 7 PB4 (ADC7/~{OC1D}/CLKI/XTAL1/PCINT12) (io), 8 PB5 (ADC8/OC1D/CLKO/XTAL2/PCINT13) (io), 10 PB6 (ADC9/INT0/T0/PCINT14) (io), 11 PB7 (ADC10/~{RESET}/PCINT15) (io), 13 PA7 (ADC6/AIN1/PCINT7) (io), 14 PA6 (ADC5/AIN0/PCINT6) (io), 15 PA5 (ADC4/AIN2/PCINT5) (io), 17 PA4 (ADC3/ICP0/PCINT4) (io), 18 AVCC (power), 21 AGND (power), 22 PA3 (AREF/PCINT3) (io), 23 PA2 (ADC2/INT1/USCK/SCL/PCINT2) (io), 25 PA1 (ADC1/DO/PCINT1) (io), 26 PA0 (ADC0/DI/SDA/PCINT0) (io), 30 PB0 (MOSI/DI/SDA/~{OC1A}/PCINT8) (io), 31 PB1 (MISO/DO/OC1A/PCINT9) (io), 32 PB2 (SCK/USCK/SCL/~{OC1B}/PCINT10) (io)
part B pins: 1 NC, 3 NC, 6 NC, 9 NC, 12 NC, 16 NC, 19 NC, 20 NC, 24 NC, 27 NC, 28 NC, 29 NC, 33 DAP (power)

## ATtiny261-ESSZ
designator U?
8-bit Automotive AVR Microcontroller, 2KB Flash, 128 Bytes EEPROM, 128 Bytes SRAM, Automotive Grade (-40°C to +125°C), 20-Pin SOIC, Engineering Sample
footprint 20TG_N (SOIC, 20-Leads, Body 12.8x7.5mm, Pitch 1.27mm, IPC Medium Density)
footprint 20TG_L (SOIC, 20-Leads, Body 12.8x7.5mm, Pitch 1.27mm, IPC High Density)
footprint 20TG_M (SOIC, 20-Leads, Body 12.8x7.5mm, Pitch 1.27mm, IPC Low Density)
pins: 1 PB0 (MOSI/DI/SDA/~{OC1A}/PCINT8) (io), 2 PB1 (MISO/DO/OC1A/PCINT9) (io), 3 PB2 (SCK/USCK/SCL/~{OC1B}/PCINT10) (io), 4 PB3 (OC1B/PCINT11) (io), 5 VCC (power), 6 GND (power), 7 PB4 (ADC7/~{OC1D}/CLKI/XTAL1/PCINT12) (io), 8 PB5 (ADC8/OC1D/CLKO/XTAL2/PCINT13) (io), 9 PB6 (ADC9/INT0/T0/PCINT14) (io), 10 PB7 (ADC10/~{RESET}/PCINT15) (io), 11 PA7 (ADC6/AIN1/PCINT7) (io), 12 PA6 (ADC5/AIN0/PCINT6) (io), 13 PA5 (ADC4/AIN2/PCINT5) (io), 14 PA4 (ADC3/ICP0/PCINT4) (io), 15 AVCC (power), 16 AGND (power), 17 PA3 (AREF/PCINT3) (io), 18 PA2 (ADC2/INT1/USCK/SCL/PCINT2) (io), 19 PA1 (ADC1/DO/PCINT1) (io), 20 PA0 (ADC0/DI/SDA/PCINT0) (io)

## ATtiny261-ESXAZ
designator U?
8-bit Automotive AVR Microcontroller, 2KB Flash, 128 Bytes EEPROM, 128 Bytes SRAM, Automotive Grade (-40°C to +125°C), 20-Pin QFN, Engineering Sample
footprint 20PC_N (QFN, 20-Leads, Body 4x4mm, Pitch 0.5mm, IPC Medium Density)
footprint 20PC_L (QFN, 20-Leads, Body 4x4mm, Pitch 0.5mm, IPC High Density)
footprint 20PC_M (QFN, 20-Leads, Body 4x4mm, Pitch 0.5mm, IPC Low Density)
pins: 1 PB2 (SCK/USCK/SCL/~{OC1B}/PCINT10) (io), 2 PB3 (OC1B/PCINT11) (io), 3 VCC (power), 4 GND (power), 5 PB4 (ADC7/~{OC1D}/CLKI/XTAL1/PCINT12) (io), 6 PB5 (ADC8/OC1D/CLKO/XTAL2/PCINT13) (io), 7 PB6 (ADC9/INT0/T0/PCINT14) (io), 8 PB7 (ADC10/~{RESET}/PCINT15) (io), 9 PA7 (ADC6/AIN1/PCINT7) (io), 10 PA6 (ADC5/AIN0/PCINT6) (io), 11 PA5 (ADC4/AIN2/PCINT5) (io), 12 PA4 (ADC3/ICP0/PCINT4) (io), 13 AVCC (power), 14 AGND (power), 15 PA3 (AREF/PCINT3) (io), 16 PA2 (ADC2/INT1/USCK/SCL/PCINT2) (io), 17 PA1 (ADC1/DO/PCINT1) (io), 18 PA0 (ADC0/DI/SDA/PCINT0) (io), 19 PB0 (MOSI/DI/SDA/~{OC1A}/PCINT8) (io), 20 PB1 (MISO/DO/OC1A/PCINT9) (io), 21 DAP (power)

## ATtiny261-ESXD
designator U?
8-bit Automotive AVR Microcontroller, 2KB Flash, 128 Bytes EEPROM, 128 Bytes SRAM, Extended Grade (-40°C to +150°C), 20-Pin TSSOP
footprint 6G_N (TSOP, 20-Leads, Body 6.5x4.4mm, Pitch 0.65mm, IPC Medium Density)
footprint 6G_L (TSOP, 20-Leads, Body 6.5x4.4mm, Pitch 0.65mm, IPC High Density)
footprint 6G_M (TSOP, 20-Leads, Body 6.5x4.4mm, Pitch 0.65mm, IPC Low Density)
pins: 1 PB0 (MOSI/DI/SDA/~{OC1A}/PCINT8) (io), 2 PB1 (MISO/DO/OC1A/PCINT9) (io), 3 PB2 (SCK/USCK/SCL/~{OC1B}/PCINT10) (io), 4 PB3 (OC1B/PCINT11) (io), 5 VCC (power), 6 GND (power), 7 PB4 (ADC7/~{OC1D}/CLKI/XTAL1/PCINT12) (io), 8 PB5 (ADC8/OC1D/CLKO/XTAL2/PCINT13) (io), 9 PB6 (ADC9/INT0/T0/PCINT14) (io), 10 PB7 (ADC10/~{RESET}/PCINT15) (io), 11 PA7 (ADC6/AIN1/PCINT7) (io), 12 PA6 (ADC5/AIN0/PCINT6) (io), 13 PA5 (ADC4/AIN2/PCINT5) (io), 14 PA4 (ADC3/ICP0/PCINT4) (io), 15 AVCC (power), 16 AGND (power), 17 PA3 (AREF/PCINT3) (io), 18 PA2 (ADC2/INT1/USCK/SCL/PCINT2) (io), 19 PA1 (ADC1/DO/PCINT1) (io), 20 PA0 (ADC0/DI/SDA/PCINT0) (io)

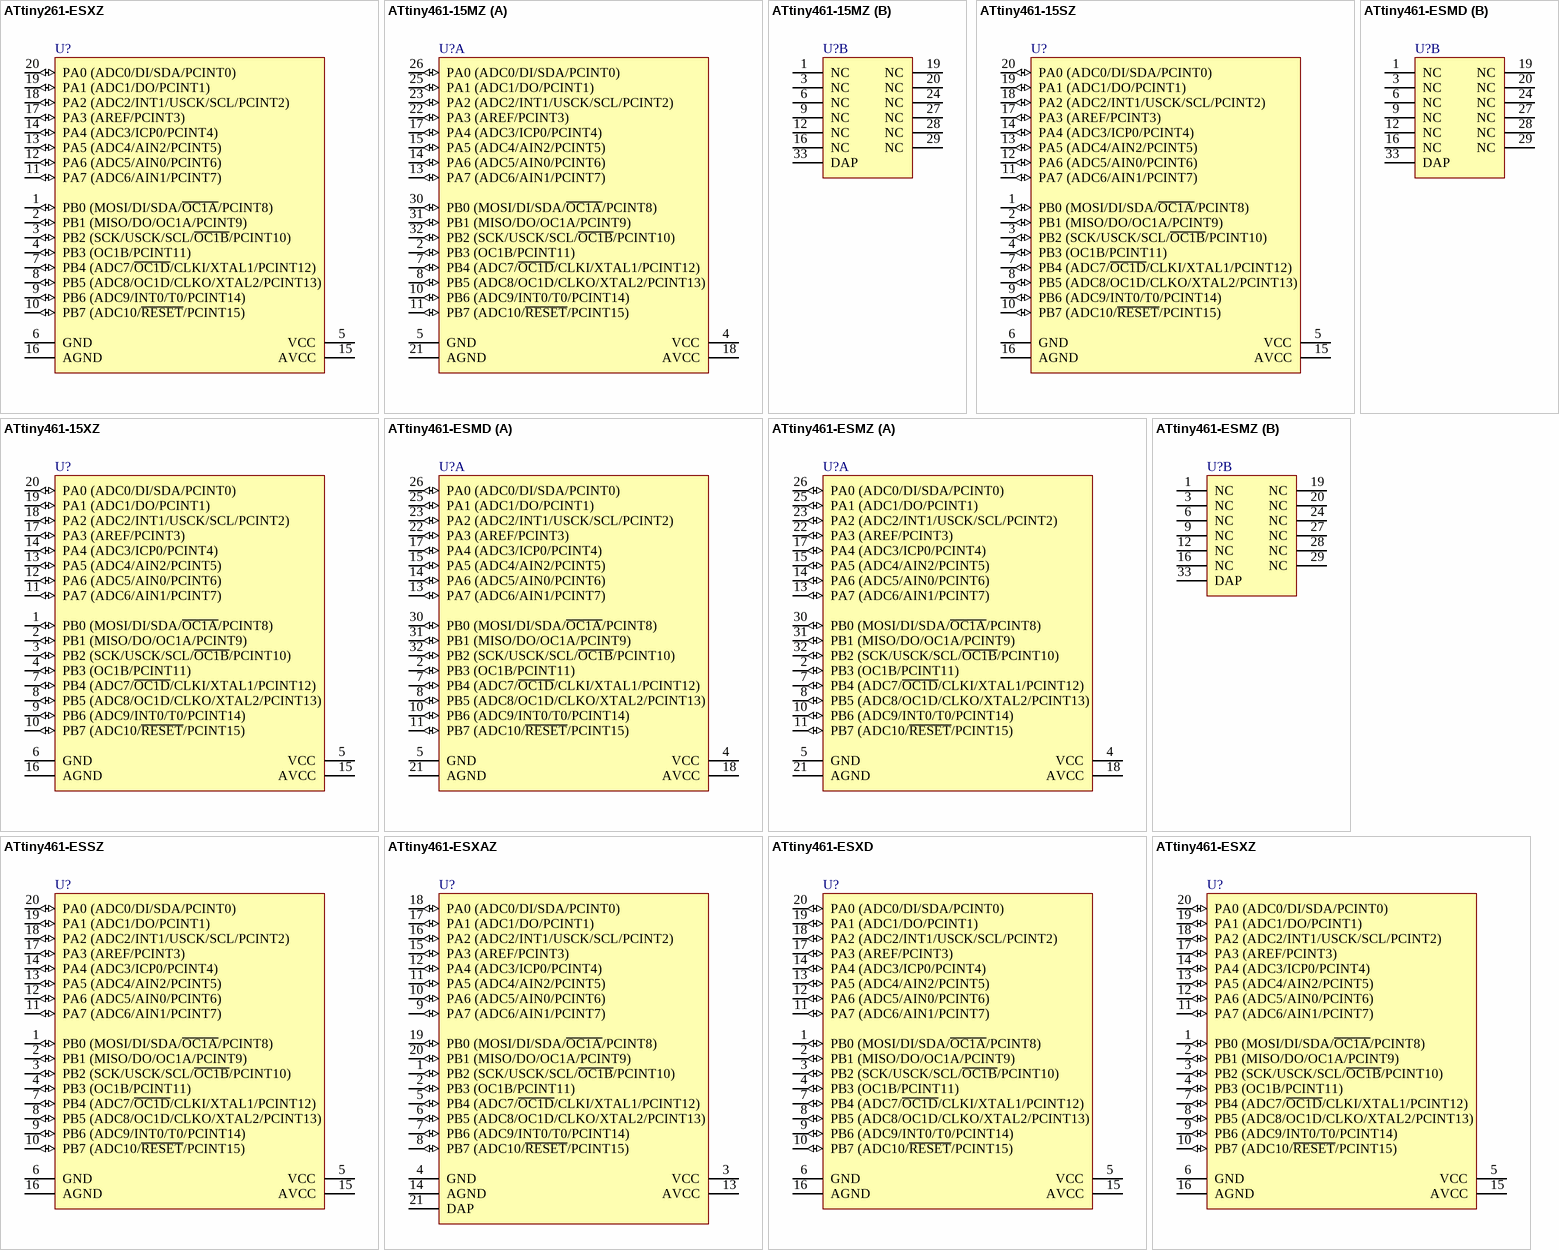
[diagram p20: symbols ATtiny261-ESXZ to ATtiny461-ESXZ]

## ATtiny261-ESXZ
designator U?
8-bit Automotive AVR Microcontroller, 2KB Flash, 128 Bytes EEPROM, 128 Bytes SRAM, Automotive Grade (-40°C to +125°C), 20-Pin TSSOP, Engineering Sample
footprint 6G_N (TSOP, 20-Leads, Body 6.5x4.4mm, Pitch 0.65mm, IPC Medium Density)
footprint 6G_L (TSOP, 20-Leads, Body 6.5x4.4mm, Pitch 0.65mm, IPC High Density)
footprint 6G_M (TSOP, 20-Leads, Body 6.5x4.4mm, Pitch 0.65mm, IPC Low Density)
pins: 1 PB0 (MOSI/DI/SDA/~{OC1A}/PCINT8) (io), 2 PB1 (MISO/DO/OC1A/PCINT9) (io), 3 PB2 (SCK/USCK/SCL/~{OC1B}/PCINT10) (io), 4 PB3 (OC1B/PCINT11) (io), 5 VCC (power), 6 GND (power), 7 PB4 (ADC7/~{OC1D}/CLKI/XTAL1/PCINT12) (io), 8 PB5 (ADC8/OC1D/CLKO/XTAL2/PCINT13) (io), 9 PB6 (ADC9/INT0/T0/PCINT14) (io), 10 PB7 (ADC10/~{RESET}/PCINT15) (io), 11 PA7 (ADC6/AIN1/PCINT7) (io), 12 PA6 (ADC5/AIN0/PCINT6) (io), 13 PA5 (ADC4/AIN2/PCINT5) (io), 14 PA4 (ADC3/ICP0/PCINT4) (io), 15 AVCC (power), 16 AGND (power), 17 PA3 (AREF/PCINT3) (io), 18 PA2 (ADC2/INT1/USCK/SCL/PCINT2) (io), 19 PA1 (ADC1/DO/PCINT1) (io), 20 PA0 (ADC0/DI/SDA/PCINT0) (io)

## ATtiny461-15MZ
designator U?
8-bit Automotive AVR Microcontroller, 4KB Flash, 256 Bytes EEPROM, 256 Bytes SRAM, Automotive Grade (-40°C to +125°C), 32-Pin VQFN
footprint 32PN_N (QFN, 32-Leads, Body 5x5mm, Pitch 0.5mm, IPC Medium Density)
footprint 32PN_L (QFN, 32-Leads, Body 5x5mm, Pitch 0.5mm, IPC High Density)
footprint 32PN_M (QFN, 32-Leads, Body 5x5mm, Pitch 0.5mm, IPC Low Density)
part A pins: 2 PB3 (OC1B/PCINT11) (io), 4 VCC (power), 5 GND (power), 7 PB4 (ADC7/~{OC1D}/CLKI/XTAL1/PCINT12) (io), 8 PB5 (ADC8/OC1D/CLKO/XTAL2/PCINT13) (io), 10 PB6 (ADC9/INT0/T0/PCINT14) (io), 11 PB7 (ADC10/~{RESET}/PCINT15) (io), 13 PA7 (ADC6/AIN1/PCINT7) (io), 14 PA6 (ADC5/AIN0/PCINT6) (io), 15 PA5 (ADC4/AIN2/PCINT5) (io), 17 PA4 (ADC3/ICP0/PCINT4) (io), 18 AVCC (power), 21 AGND (power), 22 PA3 (AREF/PCINT3) (io), 23 PA2 (ADC2/INT1/USCK/SCL/PCINT2) (io), 25 PA1 (ADC1/DO/PCINT1) (io), 26 PA0 (ADC0/DI/SDA/PCINT0) (io), 30 PB0 (MOSI/DI/SDA/~{OC1A}/PCINT8) (io), 31 PB1 (MISO/DO/OC1A/PCINT9) (io), 32 PB2 (SCK/USCK/SCL/~{OC1B}/PCINT10) (io)
part B pins: 1 NC, 3 NC, 6 NC, 9 NC, 12 NC, 16 NC, 19 NC, 20 NC, 24 NC, 27 NC, 28 NC, 29 NC, 33 DAP (power)

## ATtiny461-15SZ
designator U?
8-bit Automotive AVR Microcontroller, 4KB Flash, 256 Bytes EEPROM, 256 Bytes SRAM, Automotive Grade (-40°C to +125°C), 20-Pin SOIC
footprint 20TG_N (SOIC, 20-Leads, Body 12.8x7.5mm, Pitch 1.27mm, IPC Medium Density)
footprint 20TG_L (SOIC, 20-Leads, Body 12.8x7.5mm, Pitch 1.27mm, IPC High Density)
footprint 20TG_M (SOIC, 20-Leads, Body 12.8x7.5mm, Pitch 1.27mm, IPC Low Density)
pins: 1 PB0 (MOSI/DI/SDA/~{OC1A}/PCINT8) (io), 2 PB1 (MISO/DO/OC1A/PCINT9) (io), 3 PB2 (SCK/USCK/SCL/~{OC1B}/PCINT10) (io), 4 PB3 (OC1B/PCINT11) (io), 5 VCC (power), 6 GND (power), 7 PB4 (ADC7/~{OC1D}/CLKI/XTAL1/PCINT12) (io), 8 PB5 (ADC8/OC1D/CLKO/XTAL2/PCINT13) (io), 9 PB6 (ADC9/INT0/T0/PCINT14) (io), 10 PB7 (ADC10/~{RESET}/PCINT15) (io), 11 PA7 (ADC6/AIN1/PCINT7) (io), 12 PA6 (ADC5/AIN0/PCINT6) (io), 13 PA5 (ADC4/AIN2/PCINT5) (io), 14 PA4 (ADC3/ICP0/PCINT4) (io), 15 AVCC (power), 16 AGND (power), 17 PA3 (AREF/PCINT3) (io), 18 PA2 (ADC2/INT1/USCK/SCL/PCINT2) (io), 19 PA1 (ADC1/DO/PCINT1) (io), 20 PA0 (ADC0/DI/SDA/PCINT0) (io)

## ATtiny461-15XZ
designator U?
8-bit Automotive AVR Microcontroller, 4KB Flash, 256 Bytes EEPROM, 256 Bytes SRAM, Automotive Grade (-40°C to +125°C), 20-Pin TSSOP
footprint 6G_N (TSOP, 20-Leads, Body 6.5x4.4mm, Pitch 0.65mm, IPC Medium Density)
footprint 6G_L (TSOP, 20-Leads, Body 6.5x4.4mm, Pitch 0.65mm, IPC High Density)
footprint 6G_M (TSOP, 20-Leads, Body 6.5x4.4mm, Pitch 0.65mm, IPC Low Density)
pins: 1 PB0 (MOSI/DI/SDA/~{OC1A}/PCINT8) (io), 2 PB1 (MISO/DO/OC1A/PCINT9) (io), 3 PB2 (SCK/USCK/SCL/~{OC1B}/PCINT10) (io), 4 PB3 (OC1B/PCINT11) (io), 5 VCC (power), 6 GND (power), 7 PB4 (ADC7/~{OC1D}/CLKI/XTAL1/PCINT12) (io), 8 PB5 (ADC8/OC1D/CLKO/XTAL2/PCINT13) (io), 9 PB6 (ADC9/INT0/T0/PCINT14) (io), 10 PB7 (ADC10/~{RESET}/PCINT15) (io), 11 PA7 (ADC6/AIN1/PCINT7) (io), 12 PA6 (ADC5/AIN0/PCINT6) (io), 13 PA5 (ADC4/AIN2/PCINT5) (io), 14 PA4 (ADC3/ICP0/PCINT4) (io), 15 AVCC (power), 16 AGND (power), 17 PA3 (AREF/PCINT3) (io), 18 PA2 (ADC2/INT1/USCK/SCL/PCINT2) (io), 19 PA1 (ADC1/DO/PCINT1) (io), 20 PA0 (ADC0/DI/SDA/PCINT0) (io)

## ATtiny461-ESMD
designator U?
8-bit Automotive AVR Microcontroller, 4KB Flash, 256 Bytes EEPROM, 256 Bytes SRAM, Extended Grade (-40°C to +150°C), 32-Pin VQFN
footprint 32PN_N (QFN, 32-Leads, Body 5x5mm, Pitch 0.5mm, IPC Medium Density)
footprint 32PN_L (QFN, 32-Leads, Body 5x5mm, Pitch 0.5mm, IPC High Density)
footprint 32PN_M (QFN, 32-Leads, Body 5x5mm, Pitch 0.5mm, IPC Low Density)
part A pins: 2 PB3 (OC1B/PCINT11) (io), 4 VCC (power), 5 GND (power), 7 PB4 (ADC7/~{OC1D}/CLKI/XTAL1/PCINT12) (io), 8 PB5 (ADC8/OC1D/CLKO/XTAL2/PCINT13) (io), 10 PB6 (ADC9/INT0/T0/PCINT14) (io), 11 PB7 (ADC10/~{RESET}/PCINT15) (io), 13 PA7 (ADC6/AIN1/PCINT7) (io), 14 PA6 (ADC5/AIN0/PCINT6) (io), 15 PA5 (ADC4/AIN2/PCINT5) (io), 17 PA4 (ADC3/ICP0/PCINT4) (io), 18 AVCC (power), 21 AGND (power), 22 PA3 (AREF/PCINT3) (io), 23 PA2 (ADC2/INT1/USCK/SCL/PCINT2) (io), 25 PA1 (ADC1/DO/PCINT1) (io), 26 PA0 (ADC0/DI/SDA/PCINT0) (io), 30 PB0 (MOSI/DI/SDA/~{OC1A}/PCINT8) (io), 31 PB1 (MISO/DO/OC1A/PCINT9) (io), 32 PB2 (SCK/USCK/SCL/~{OC1B}/PCINT10) (io)
part B pins: 1 NC, 3 NC, 6 NC, 9 NC, 12 NC, 16 NC, 19 NC, 20 NC, 24 NC, 27 NC, 28 NC, 29 NC, 33 DAP (power)

## ATtiny461-ESMZ
designator U?
8-bit Automotive AVR Microcontroller, 4KB Flash, 256 Bytes EEPROM, 256 Bytes SRAM, Automotive Grade (-40°C to +125°C), 32-Pin VQFN, Engineering Sample
footprint 32PN_N (QFN, 32-Leads, Body 5x5mm, Pitch 0.5mm, IPC Medium Density)
footprint 32PN_L (QFN, 32-Leads, Body 5x5mm, Pitch 0.5mm, IPC High Density)
footprint 32PN_M (QFN, 32-Leads, Body 5x5mm, Pitch 0.5mm, IPC Low Density)
part A pins: 2 PB3 (OC1B/PCINT11) (io), 4 VCC (power), 5 GND (power), 7 PB4 (ADC7/~{OC1D}/CLKI/XTAL1/PCINT12) (io), 8 PB5 (ADC8/OC1D/CLKO/XTAL2/PCINT13) (io), 10 PB6 (ADC9/INT0/T0/PCINT14) (io), 11 PB7 (ADC10/~{RESET}/PCINT15) (io), 13 PA7 (ADC6/AIN1/PCINT7) (io), 14 PA6 (ADC5/AIN0/PCINT6) (io), 15 PA5 (ADC4/AIN2/PCINT5) (io), 17 PA4 (ADC3/ICP0/PCINT4) (io), 18 AVCC (power), 21 AGND (power), 22 PA3 (AREF/PCINT3) (io), 23 PA2 (ADC2/INT1/USCK/SCL/PCINT2) (io), 25 PA1 (ADC1/DO/PCINT1) (io), 26 PA0 (ADC0/DI/SDA/PCINT0) (io), 30 PB0 (MOSI/DI/SDA/~{OC1A}/PCINT8) (io), 31 PB1 (MISO/DO/OC1A/PCINT9) (io), 32 PB2 (SCK/USCK/SCL/~{OC1B}/PCINT10) (io)
part B pins: 1 NC, 3 NC, 6 NC, 9 NC, 12 NC, 16 NC, 19 NC, 20 NC, 24 NC, 27 NC, 28 NC, 29 NC, 33 DAP (power)

## ATtiny461-ESSZ
designator U?
8-bit Automotive AVR Microcontroller, 4KB Flash, 256 Bytes EEPROM, 256 Bytes SRAM, Automotive Grade (-40°C to +125°C), 20-Pin SOIC, Engineering Sample
footprint 20TG_N (SOIC, 20-Leads, Body 12.8x7.5mm, Pitch 1.27mm, IPC Medium Density)
footprint 20TG_L (SOIC, 20-Leads, Body 12.8x7.5mm, Pitch 1.27mm, IPC High Density)
footprint 20TG_M (SOIC, 20-Leads, Body 12.8x7.5mm, Pitch 1.27mm, IPC Low Density)
pins: 1 PB0 (MOSI/DI/SDA/~{OC1A}/PCINT8) (io), 2 PB1 (MISO/DO/OC1A/PCINT9) (io), 3 PB2 (SCK/USCK/SCL/~{OC1B}/PCINT10) (io), 4 PB3 (OC1B/PCINT11) (io), 5 VCC (power), 6 GND (power), 7 PB4 (ADC7/~{OC1D}/CLKI/XTAL1/PCINT12) (io), 8 PB5 (ADC8/OC1D/CLKO/XTAL2/PCINT13) (io), 9 PB6 (ADC9/INT0/T0/PCINT14) (io), 10 PB7 (ADC10/~{RESET}/PCINT15) (io), 11 PA7 (ADC6/AIN1/PCINT7) (io), 12 PA6 (ADC5/AIN0/PCINT6) (io), 13 PA5 (ADC4/AIN2/PCINT5) (io), 14 PA4 (ADC3/ICP0/PCINT4) (io), 15 AVCC (power), 16 AGND (power), 17 PA3 (AREF/PCINT3) (io), 18 PA2 (ADC2/INT1/USCK/SCL/PCINT2) (io), 19 PA1 (ADC1/DO/PCINT1) (io), 20 PA0 (ADC0/DI/SDA/PCINT0) (io)

## ATtiny461-ESXAZ
designator U?
8-bit Automotive AVR Microcontroller, 4KB Flash, 256 Bytes EEPROM, 256 Bytes SRAM, Automotive Grade (-40°C to +125°C), 20-Pin QFN, Engineering Sample
footprint 20PC_N (QFN, 20-Leads, Body 4x4mm, Pitch 0.5mm, IPC Medium Density)
footprint 20PC_L (QFN, 20-Leads, Body 4x4mm, Pitch 0.5mm, IPC High Density)
footprint 20PC_M (QFN, 20-Leads, Body 4x4mm, Pitch 0.5mm, IPC Low Density)
pins: 1 PB2 (SCK/USCK/SCL/~{OC1B}/PCINT10) (io), 2 PB3 (OC1B/PCINT11) (io), 3 VCC (power), 4 GND (power), 5 PB4 (ADC7/~{OC1D}/CLKI/XTAL1/PCINT12) (io), 6 PB5 (ADC8/OC1D/CLKO/XTAL2/PCINT13) (io), 7 PB6 (ADC9/INT0/T0/PCINT14) (io), 8 PB7 (ADC10/~{RESET}/PCINT15) (io), 9 PA7 (ADC6/AIN1/PCINT7) (io), 10 PA6 (ADC5/AIN0/PCINT6) (io), 11 PA5 (ADC4/AIN2/PCINT5) (io), 12 PA4 (ADC3/ICP0/PCINT4) (io), 13 AVCC (power), 14 AGND (power), 15 PA3 (AREF/PCINT3) (io), 16 PA2 (ADC2/INT1/USCK/SCL/PCINT2) (io), 17 PA1 (ADC1/DO/PCINT1) (io), 18 PA0 (ADC0/DI/SDA/PCINT0) (io), 19 PB0 (MOSI/DI/SDA/~{OC1A}/PCINT8) (io), 20 PB1 (MISO/DO/OC1A/PCINT9) (io), 21 DAP (power)

## ATtiny461-ESXD
designator U?
8-bit Automotive AVR Microcontroller, 4KB Flash, 256 Bytes EEPROM, 256 Bytes SRAM, Extended Grade (-40°C to +150°C), 20-Pin TSSOP
footprint 6G_N (TSOP, 20-Leads, Body 6.5x4.4mm, Pitch 0.65mm, IPC Medium Density)
footprint 6G_L (TSOP, 20-Leads, Body 6.5x4.4mm, Pitch 0.65mm, IPC High Density)
footprint 6G_M (TSOP, 20-Leads, Body 6.5x4.4mm, Pitch 0.65mm, IPC Low Density)
pins: 1 PB0 (MOSI/DI/SDA/~{OC1A}/PCINT8) (io), 2 PB1 (MISO/DO/OC1A/PCINT9) (io), 3 PB2 (SCK/USCK/SCL/~{OC1B}/PCINT10) (io), 4 PB3 (OC1B/PCINT11) (io), 5 VCC (power), 6 GND (power), 7 PB4 (ADC7/~{OC1D}/CLKI/XTAL1/PCINT12) (io), 8 PB5 (ADC8/OC1D/CLKO/XTAL2/PCINT13) (io), 9 PB6 (ADC9/INT0/T0/PCINT14) (io), 10 PB7 (ADC10/~{RESET}/PCINT15) (io), 11 PA7 (ADC6/AIN1/PCINT7) (io), 12 PA6 (ADC5/AIN0/PCINT6) (io), 13 PA5 (ADC4/AIN2/PCINT5) (io), 14 PA4 (ADC3/ICP0/PCINT4) (io), 15 AVCC (power), 16 AGND (power), 17 PA3 (AREF/PCINT3) (io), 18 PA2 (ADC2/INT1/USCK/SCL/PCINT2) (io), 19 PA1 (ADC1/DO/PCINT1) (io), 20 PA0 (ADC0/DI/SDA/PCINT0) (io)

## ATtiny461-ESXZ
designator U?
8-bit Automotive AVR Microcontroller, 4KB Flash, 256 Bytes EEPROM, 256 Bytes SRAM, Automotive Grade (-40°C to +125°C), 20-Pin TSSOP, Engineering Sample
footprint 6G_N (TSOP, 20-Leads, Body 6.5x4.4mm, Pitch 0.65mm, IPC Medium Density)
footprint 6G_L (TSOP, 20-Leads, Body 6.5x4.4mm, Pitch 0.65mm, IPC High Density)
footprint 6G_M (TSOP, 20-Leads, Body 6.5x4.4mm, Pitch 0.65mm, IPC Low Density)
pins: 1 PB0 (MOSI/DI/SDA/~{OC1A}/PCINT8) (io), 2 PB1 (MISO/DO/OC1A/PCINT9) (io), 3 PB2 (SCK/USCK/SCL/~{OC1B}/PCINT10) (io), 4 PB3 (OC1B/PCINT11) (io), 5 VCC (power), 6 GND (power), 7 PB4 (ADC7/~{OC1D}/CLKI/XTAL1/PCINT12) (io), 8 PB5 (ADC8/OC1D/CLKO/XTAL2/PCINT13) (io), 9 PB6 (ADC9/INT0/T0/PCINT14) (io), 10 PB7 (ADC10/~{RESET}/PCINT15) (io), 11 PA7 (ADC6/AIN1/PCINT7) (io), 12 PA6 (ADC5/AIN0/PCINT6) (io), 13 PA5 (ADC4/AIN2/PCINT5) (io), 14 PA4 (ADC3/ICP0/PCINT4) (io), 15 AVCC (power), 16 AGND (power), 17 PA3 (AREF/PCINT3) (io), 18 PA2 (ADC2/INT1/USCK/SCL/PCINT2) (io), 19 PA1 (ADC1/DO/PCINT1) (io), 20 PA0 (ADC0/DI/SDA/PCINT0) (io)

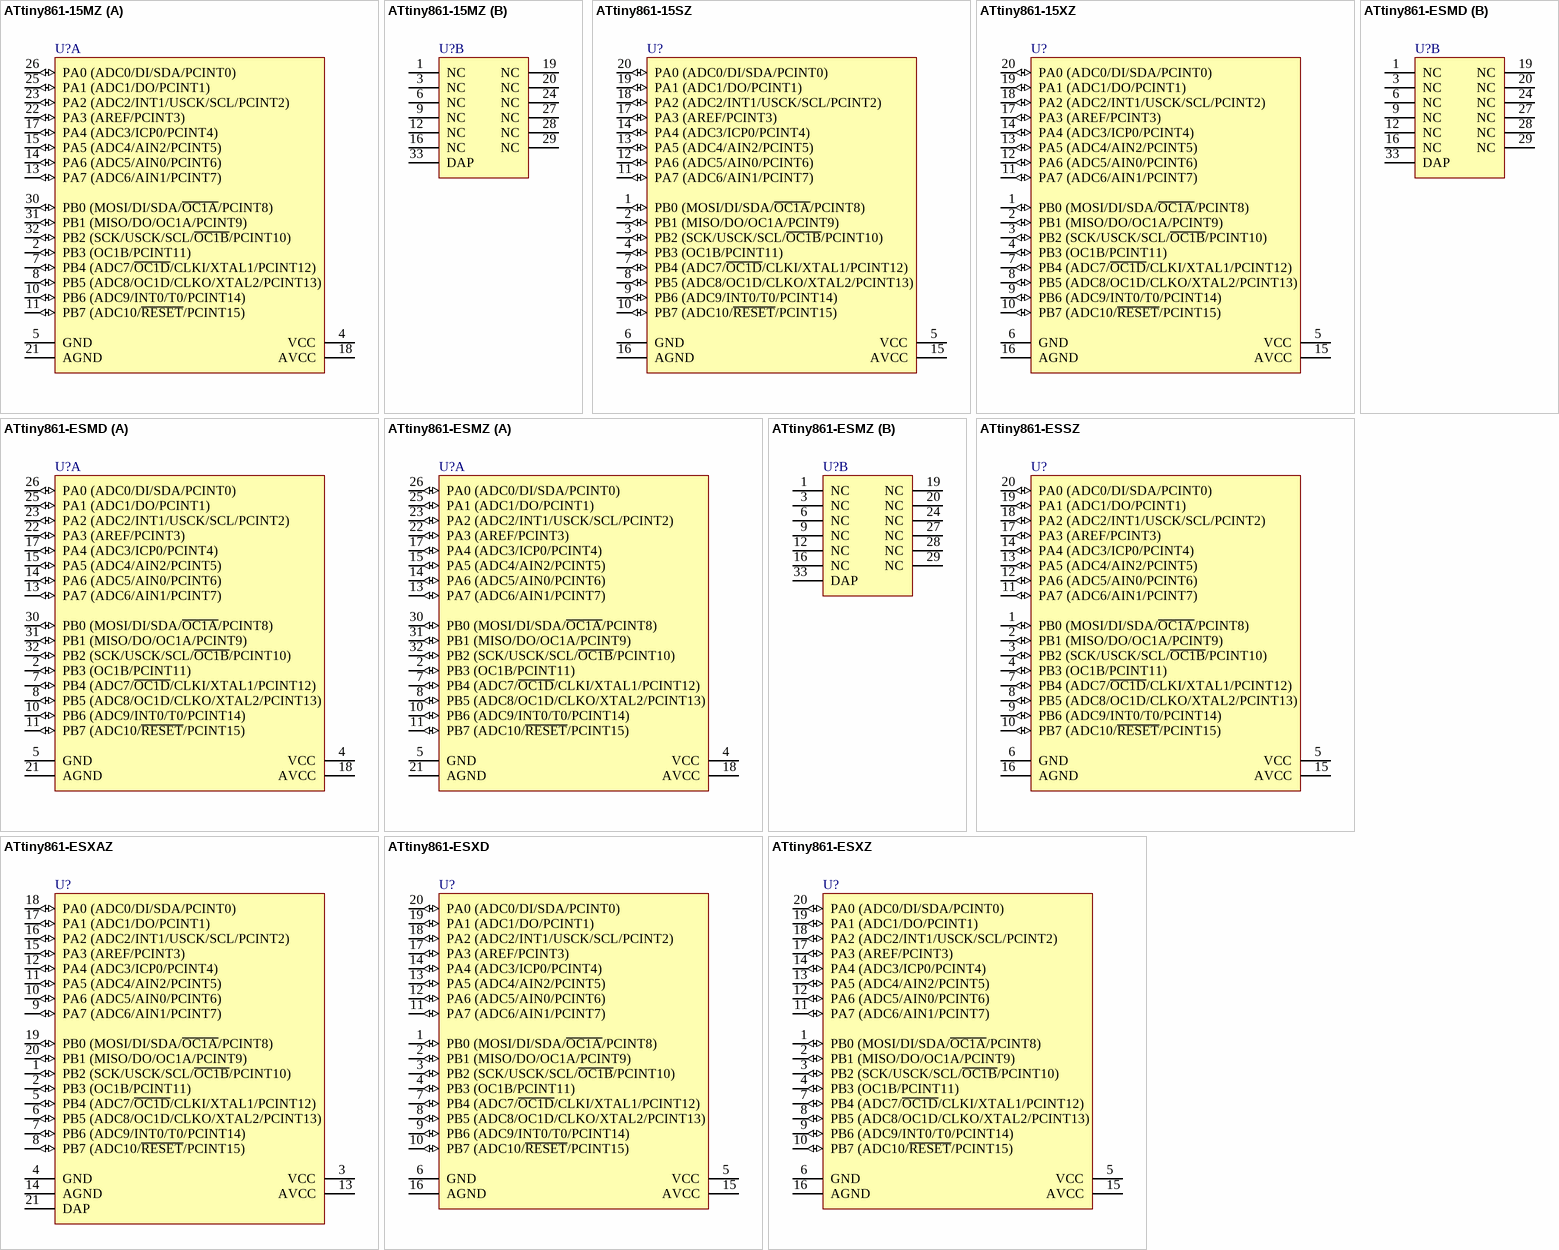
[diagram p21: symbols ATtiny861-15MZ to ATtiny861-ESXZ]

## ATtiny861-15MZ
designator U?
8-bit Automotive AVR Microcontroller, 8KB Flash, 512 Bytes EEPROM, 512 Bytes SRAM, Automotive Grade (-40°C to +125°C), 32-Pin VQFN
footprint 32PN_N (QFN, 32-Leads, Body 5x5mm, Pitch 0.5mm, IPC Medium Density)
footprint 32PN_L (QFN, 32-Leads, Body 5x5mm, Pitch 0.5mm, IPC High Density)
footprint 32PN_M (QFN, 32-Leads, Body 5x5mm, Pitch 0.5mm, IPC Low Density)
part A pins: 2 PB3 (OC1B/PCINT11) (io), 4 VCC (power), 5 GND (power), 7 PB4 (ADC7/~{OC1D}/CLKI/XTAL1/PCINT12) (io), 8 PB5 (ADC8/OC1D/CLKO/XTAL2/PCINT13) (io), 10 PB6 (ADC9/INT0/T0/PCINT14) (io), 11 PB7 (ADC10/~{RESET}/PCINT15) (io), 13 PA7 (ADC6/AIN1/PCINT7) (io), 14 PA6 (ADC5/AIN0/PCINT6) (io), 15 PA5 (ADC4/AIN2/PCINT5) (io), 17 PA4 (ADC3/ICP0/PCINT4) (io), 18 AVCC (power), 21 AGND (power), 22 PA3 (AREF/PCINT3) (io), 23 PA2 (ADC2/INT1/USCK/SCL/PCINT2) (io), 25 PA1 (ADC1/DO/PCINT1) (io), 26 PA0 (ADC0/DI/SDA/PCINT0) (io), 30 PB0 (MOSI/DI/SDA/~{OC1A}/PCINT8) (io), 31 PB1 (MISO/DO/OC1A/PCINT9) (io), 32 PB2 (SCK/USCK/SCL/~{OC1B}/PCINT10) (io)
part B pins: 1 NC, 3 NC, 6 NC, 9 NC, 12 NC, 16 NC, 19 NC, 20 NC, 24 NC, 27 NC, 28 NC, 29 NC, 33 DAP (power)

## ATtiny861-15SZ
designator U?
8-bit Automotive AVR Microcontroller, 8KB Flash, 512 Bytes EEPROM, 512 Bytes SRAM, Automotive Grade (-40°C to +125°C), 20-Pin SOIC
footprint 20TG_N (SOIC, 20-Leads, Body 12.8x7.5mm, Pitch 1.27mm, IPC Medium Density)
footprint 20TG_L (SOIC, 20-Leads, Body 12.8x7.5mm, Pitch 1.27mm, IPC High Density)
footprint 20TG_M (SOIC, 20-Leads, Body 12.8x7.5mm, Pitch 1.27mm, IPC Low Density)
pins: 1 PB0 (MOSI/DI/SDA/~{OC1A}/PCINT8) (io), 2 PB1 (MISO/DO/OC1A/PCINT9) (io), 3 PB2 (SCK/USCK/SCL/~{OC1B}/PCINT10) (io), 4 PB3 (OC1B/PCINT11) (io), 5 VCC (power), 6 GND (power), 7 PB4 (ADC7/~{OC1D}/CLKI/XTAL1/PCINT12) (io), 8 PB5 (ADC8/OC1D/CLKO/XTAL2/PCINT13) (io), 9 PB6 (ADC9/INT0/T0/PCINT14) (io), 10 PB7 (ADC10/~{RESET}/PCINT15) (io), 11 PA7 (ADC6/AIN1/PCINT7) (io), 12 PA6 (ADC5/AIN0/PCINT6) (io), 13 PA5 (ADC4/AIN2/PCINT5) (io), 14 PA4 (ADC3/ICP0/PCINT4) (io), 15 AVCC (power), 16 AGND (power), 17 PA3 (AREF/PCINT3) (io), 18 PA2 (ADC2/INT1/USCK/SCL/PCINT2) (io), 19 PA1 (ADC1/DO/PCINT1) (io), 20 PA0 (ADC0/DI/SDA/PCINT0) (io)

## ATtiny861-15XZ
designator U?
8-bit Automotive AVR Microcontroller, 8KB Flash, 512 Bytes EEPROM, 512 Bytes SRAM, Automotive Grade (-40°C to +125°C), 20-Pin TSSOP
footprint 6G_N (TSOP, 20-Leads, Body 6.5x4.4mm, Pitch 0.65mm, IPC Medium Density)
footprint 6G_L (TSOP, 20-Leads, Body 6.5x4.4mm, Pitch 0.65mm, IPC High Density)
footprint 6G_M (TSOP, 20-Leads, Body 6.5x4.4mm, Pitch 0.65mm, IPC Low Density)
pins: 1 PB0 (MOSI/DI/SDA/~{OC1A}/PCINT8) (io), 2 PB1 (MISO/DO/OC1A/PCINT9) (io), 3 PB2 (SCK/USCK/SCL/~{OC1B}/PCINT10) (io), 4 PB3 (OC1B/PCINT11) (io), 5 VCC (power), 6 GND (power), 7 PB4 (ADC7/~{OC1D}/CLKI/XTAL1/PCINT12) (io), 8 PB5 (ADC8/OC1D/CLKO/XTAL2/PCINT13) (io), 9 PB6 (ADC9/INT0/T0/PCINT14) (io), 10 PB7 (ADC10/~{RESET}/PCINT15) (io), 11 PA7 (ADC6/AIN1/PCINT7) (io), 12 PA6 (ADC5/AIN0/PCINT6) (io), 13 PA5 (ADC4/AIN2/PCINT5) (io), 14 PA4 (ADC3/ICP0/PCINT4) (io), 15 AVCC (power), 16 AGND (power), 17 PA3 (AREF/PCINT3) (io), 18 PA2 (ADC2/INT1/USCK/SCL/PCINT2) (io), 19 PA1 (ADC1/DO/PCINT1) (io), 20 PA0 (ADC0/DI/SDA/PCINT0) (io)

## ATtiny861-ESMD
designator U?
8-bit Automotive AVR Microcontroller, 8KB Flash, 512 Bytes EEPROM, 512 Bytes SRAM, Extended Grade (-40°C to +150°C), 32-Pin VQFN
footprint 32PN_N (QFN, 32-Leads, Body 5x5mm, Pitch 0.5mm, IPC Medium Density)
footprint 32PN_L (QFN, 32-Leads, Body 5x5mm, Pitch 0.5mm, IPC High Density)
footprint 32PN_M (QFN, 32-Leads, Body 5x5mm, Pitch 0.5mm, IPC Low Density)
part A pins: 2 PB3 (OC1B/PCINT11) (io), 4 VCC (power), 5 GND (power), 7 PB4 (ADC7/~{OC1D}/CLKI/XTAL1/PCINT12) (io), 8 PB5 (ADC8/OC1D/CLKO/XTAL2/PCINT13) (io), 10 PB6 (ADC9/INT0/T0/PCINT14) (io), 11 PB7 (ADC10/~{RESET}/PCINT15) (io), 13 PA7 (ADC6/AIN1/PCINT7) (io), 14 PA6 (ADC5/AIN0/PCINT6) (io), 15 PA5 (ADC4/AIN2/PCINT5) (io), 17 PA4 (ADC3/ICP0/PCINT4) (io), 18 AVCC (power), 21 AGND (power), 22 PA3 (AREF/PCINT3) (io), 23 PA2 (ADC2/INT1/USCK/SCL/PCINT2) (io), 25 PA1 (ADC1/DO/PCINT1) (io), 26 PA0 (ADC0/DI/SDA/PCINT0) (io), 30 PB0 (MOSI/DI/SDA/~{OC1A}/PCINT8) (io), 31 PB1 (MISO/DO/OC1A/PCINT9) (io), 32 PB2 (SCK/USCK/SCL/~{OC1B}/PCINT10) (io)
part B pins: 1 NC, 3 NC, 6 NC, 9 NC, 12 NC, 16 NC, 19 NC, 20 NC, 24 NC, 27 NC, 28 NC, 29 NC, 33 DAP (power)

## ATtiny861-ESMZ
designator U?
8-bit Automotive AVR Microcontroller, 8KB Flash, 512 Bytes EEPROM, 512 Bytes SRAM, Automotive Grade (-40°C to +125°C), 32-Pin VQFN, Engineering Sample
footprint 32PN_N (QFN, 32-Leads, Body 5x5mm, Pitch 0.5mm, IPC Medium Density)
footprint 32PN_L (QFN, 32-Leads, Body 5x5mm, Pitch 0.5mm, IPC High Density)
footprint 32PN_M (QFN, 32-Leads, Body 5x5mm, Pitch 0.5mm, IPC Low Density)
part A pins: 2 PB3 (OC1B/PCINT11) (io), 4 VCC (power), 5 GND (power), 7 PB4 (ADC7/~{OC1D}/CLKI/XTAL1/PCINT12) (io), 8 PB5 (ADC8/OC1D/CLKO/XTAL2/PCINT13) (io), 10 PB6 (ADC9/INT0/T0/PCINT14) (io), 11 PB7 (ADC10/~{RESET}/PCINT15) (io), 13 PA7 (ADC6/AIN1/PCINT7) (io), 14 PA6 (ADC5/AIN0/PCINT6) (io), 15 PA5 (ADC4/AIN2/PCINT5) (io), 17 PA4 (ADC3/ICP0/PCINT4) (io), 18 AVCC (power), 21 AGND (power), 22 PA3 (AREF/PCINT3) (io), 23 PA2 (ADC2/INT1/USCK/SCL/PCINT2) (io), 25 PA1 (ADC1/DO/PCINT1) (io), 26 PA0 (ADC0/DI/SDA/PCINT0) (io), 30 PB0 (MOSI/DI/SDA/~{OC1A}/PCINT8) (io), 31 PB1 (MISO/DO/OC1A/PCINT9) (io), 32 PB2 (SCK/USCK/SCL/~{OC1B}/PCINT10) (io)
part B pins: 1 NC, 3 NC, 6 NC, 9 NC, 12 NC, 16 NC, 19 NC, 20 NC, 24 NC, 27 NC, 28 NC, 29 NC, 33 DAP (power)

## ATtiny861-ESSZ
designator U?
8-bit Automotive AVR Microcontroller, 8KB Flash, 512 Bytes EEPROM, 512 Bytes SRAM, Automotive Grade (-40°C to +125°C), 20-Pin SOIC, Engineering Sample
footprint 20TG_N (SOIC, 20-Leads, Body 12.8x7.5mm, Pitch 1.27mm, IPC Medium Density)
footprint 20TG_L (SOIC, 20-Leads, Body 12.8x7.5mm, Pitch 1.27mm, IPC High Density)
footprint 20TG_M (SOIC, 20-Leads, Body 12.8x7.5mm, Pitch 1.27mm, IPC Low Density)
pins: 1 PB0 (MOSI/DI/SDA/~{OC1A}/PCINT8) (io), 2 PB1 (MISO/DO/OC1A/PCINT9) (io), 3 PB2 (SCK/USCK/SCL/~{OC1B}/PCINT10) (io), 4 PB3 (OC1B/PCINT11) (io), 5 VCC (power), 6 GND (power), 7 PB4 (ADC7/~{OC1D}/CLKI/XTAL1/PCINT12) (io), 8 PB5 (ADC8/OC1D/CLKO/XTAL2/PCINT13) (io), 9 PB6 (ADC9/INT0/T0/PCINT14) (io), 10 PB7 (ADC10/~{RESET}/PCINT15) (io), 11 PA7 (ADC6/AIN1/PCINT7) (io), 12 PA6 (ADC5/AIN0/PCINT6) (io), 13 PA5 (ADC4/AIN2/PCINT5) (io), 14 PA4 (ADC3/ICP0/PCINT4) (io), 15 AVCC (power), 16 AGND (power), 17 PA3 (AREF/PCINT3) (io), 18 PA2 (ADC2/INT1/USCK/SCL/PCINT2) (io), 19 PA1 (ADC1/DO/PCINT1) (io), 20 PA0 (ADC0/DI/SDA/PCINT0) (io)

## ATtiny861-ESXAZ
designator U?
8-bit Automotive AVR Microcontroller, 8KB Flash, 512 Bytes EEPROM, 512 Bytes SRAM, Automotive Grade (-40°C to +125°C), 20-Pin QFN, Engineering Sample
footprint 20PC_N (QFN, 20-Leads, Body 4x4mm, Pitch 0.5mm, IPC Medium Density)
footprint 20PC_L (QFN, 20-Leads, Body 4x4mm, Pitch 0.5mm, IPC High Density)
footprint 20PC_M (QFN, 20-Leads, Body 4x4mm, Pitch 0.5mm, IPC Low Density)
pins: 1 PB2 (SCK/USCK/SCL/~{OC1B}/PCINT10) (io), 2 PB3 (OC1B/PCINT11) (io), 3 VCC (power), 4 GND (power), 5 PB4 (ADC7/~{OC1D}/CLKI/XTAL1/PCINT12) (io), 6 PB5 (ADC8/OC1D/CLKO/XTAL2/PCINT13) (io), 7 PB6 (ADC9/INT0/T0/PCINT14) (io), 8 PB7 (ADC10/~{RESET}/PCINT15) (io), 9 PA7 (ADC6/AIN1/PCINT7) (io), 10 PA6 (ADC5/AIN0/PCINT6) (io), 11 PA5 (ADC4/AIN2/PCINT5) (io), 12 PA4 (ADC3/ICP0/PCINT4) (io), 13 AVCC (power), 14 AGND (power), 15 PA3 (AREF/PCINT3) (io), 16 PA2 (ADC2/INT1/USCK/SCL/PCINT2) (io), 17 PA1 (ADC1/DO/PCINT1) (io), 18 PA0 (ADC0/DI/SDA/PCINT0) (io), 19 PB0 (MOSI/DI/SDA/~{OC1A}/PCINT8) (io), 20 PB1 (MISO/DO/OC1A/PCINT9) (io), 21 DAP (power)

## ATtiny861-ESXD
designator U?
8-bit Automotive AVR Microcontroller, 8KB Flash, 512 Bytes EEPROM, 512 Bytes SRAM, Extended Grade (-40°C to +150°C), 20-Pin TSSOP
footprint 6G_N (TSOP, 20-Leads, Body 6.5x4.4mm, Pitch 0.65mm, IPC Medium Density)
footprint 6G_L (TSOP, 20-Leads, Body 6.5x4.4mm, Pitch 0.65mm, IPC High Density)
footprint 6G_M (TSOP, 20-Leads, Body 6.5x4.4mm, Pitch 0.65mm, IPC Low Density)
pins: 1 PB0 (MOSI/DI/SDA/~{OC1A}/PCINT8) (io), 2 PB1 (MISO/DO/OC1A/PCINT9) (io), 3 PB2 (SCK/USCK/SCL/~{OC1B}/PCINT10) (io), 4 PB3 (OC1B/PCINT11) (io), 5 VCC (power), 6 GND (power), 7 PB4 (ADC7/~{OC1D}/CLKI/XTAL1/PCINT12) (io), 8 PB5 (ADC8/OC1D/CLKO/XTAL2/PCINT13) (io), 9 PB6 (ADC9/INT0/T0/PCINT14) (io), 10 PB7 (ADC10/~{RESET}/PCINT15) (io), 11 PA7 (ADC6/AIN1/PCINT7) (io), 12 PA6 (ADC5/AIN0/PCINT6) (io), 13 PA5 (ADC4/AIN2/PCINT5) (io), 14 PA4 (ADC3/ICP0/PCINT4) (io), 15 AVCC (power), 16 AGND (power), 17 PA3 (AREF/PCINT3) (io), 18 PA2 (ADC2/INT1/USCK/SCL/PCINT2) (io), 19 PA1 (ADC1/DO/PCINT1) (io), 20 PA0 (ADC0/DI/SDA/PCINT0) (io)

## ATtiny861-ESXZ
designator U?
8-bit Automotive AVR Microcontroller, 8KB Flash, 512 Bytes EEPROM, 512 Bytes SRAM, Automotive Grade (-40°C to +125°C), 20-Pin TSSOP, Engineering Sample
footprint 6G_N (TSOP, 20-Leads, Body 6.5x4.4mm, Pitch 0.65mm, IPC Medium Density)
footprint 6G_L (TSOP, 20-Leads, Body 6.5x4.4mm, Pitch 0.65mm, IPC High Density)
footprint 6G_M (TSOP, 20-Leads, Body 6.5x4.4mm, Pitch 0.65mm, IPC Low Density)
pins: 1 PB0 (MOSI/DI/SDA/~{OC1A}/PCINT8) (io), 2 PB1 (MISO/DO/OC1A/PCINT9) (io), 3 PB2 (SCK/USCK/SCL/~{OC1B}/PCINT10) (io), 4 PB3 (OC1B/PCINT11) (io), 5 VCC (power), 6 GND (power), 7 PB4 (ADC7/~{OC1D}/CLKI/XTAL1/PCINT12) (io), 8 PB5 (ADC8/OC1D/CLKO/XTAL2/PCINT13) (io), 9 PB6 (ADC9/INT0/T0/PCINT14) (io), 10 PB7 (ADC10/~{RESET}/PCINT15) (io), 11 PA7 (ADC6/AIN1/PCINT7) (io), 12 PA6 (ADC5/AIN0/PCINT6) (io), 13 PA5 (ADC4/AIN2/PCINT5) (io), 14 PA4 (ADC3/ICP0/PCINT4) (io), 15 AVCC (power), 16 AGND (power), 17 PA3 (AREF/PCINT3) (io), 18 PA2 (ADC2/INT1/USCK/SCL/PCINT2) (io), 19 PA1 (ADC1/DO/PCINT1) (io), 20 PA0 (ADC0/DI/SDA/PCINT0) (io)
